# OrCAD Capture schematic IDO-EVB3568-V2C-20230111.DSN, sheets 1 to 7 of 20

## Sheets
1 P01. Revision History
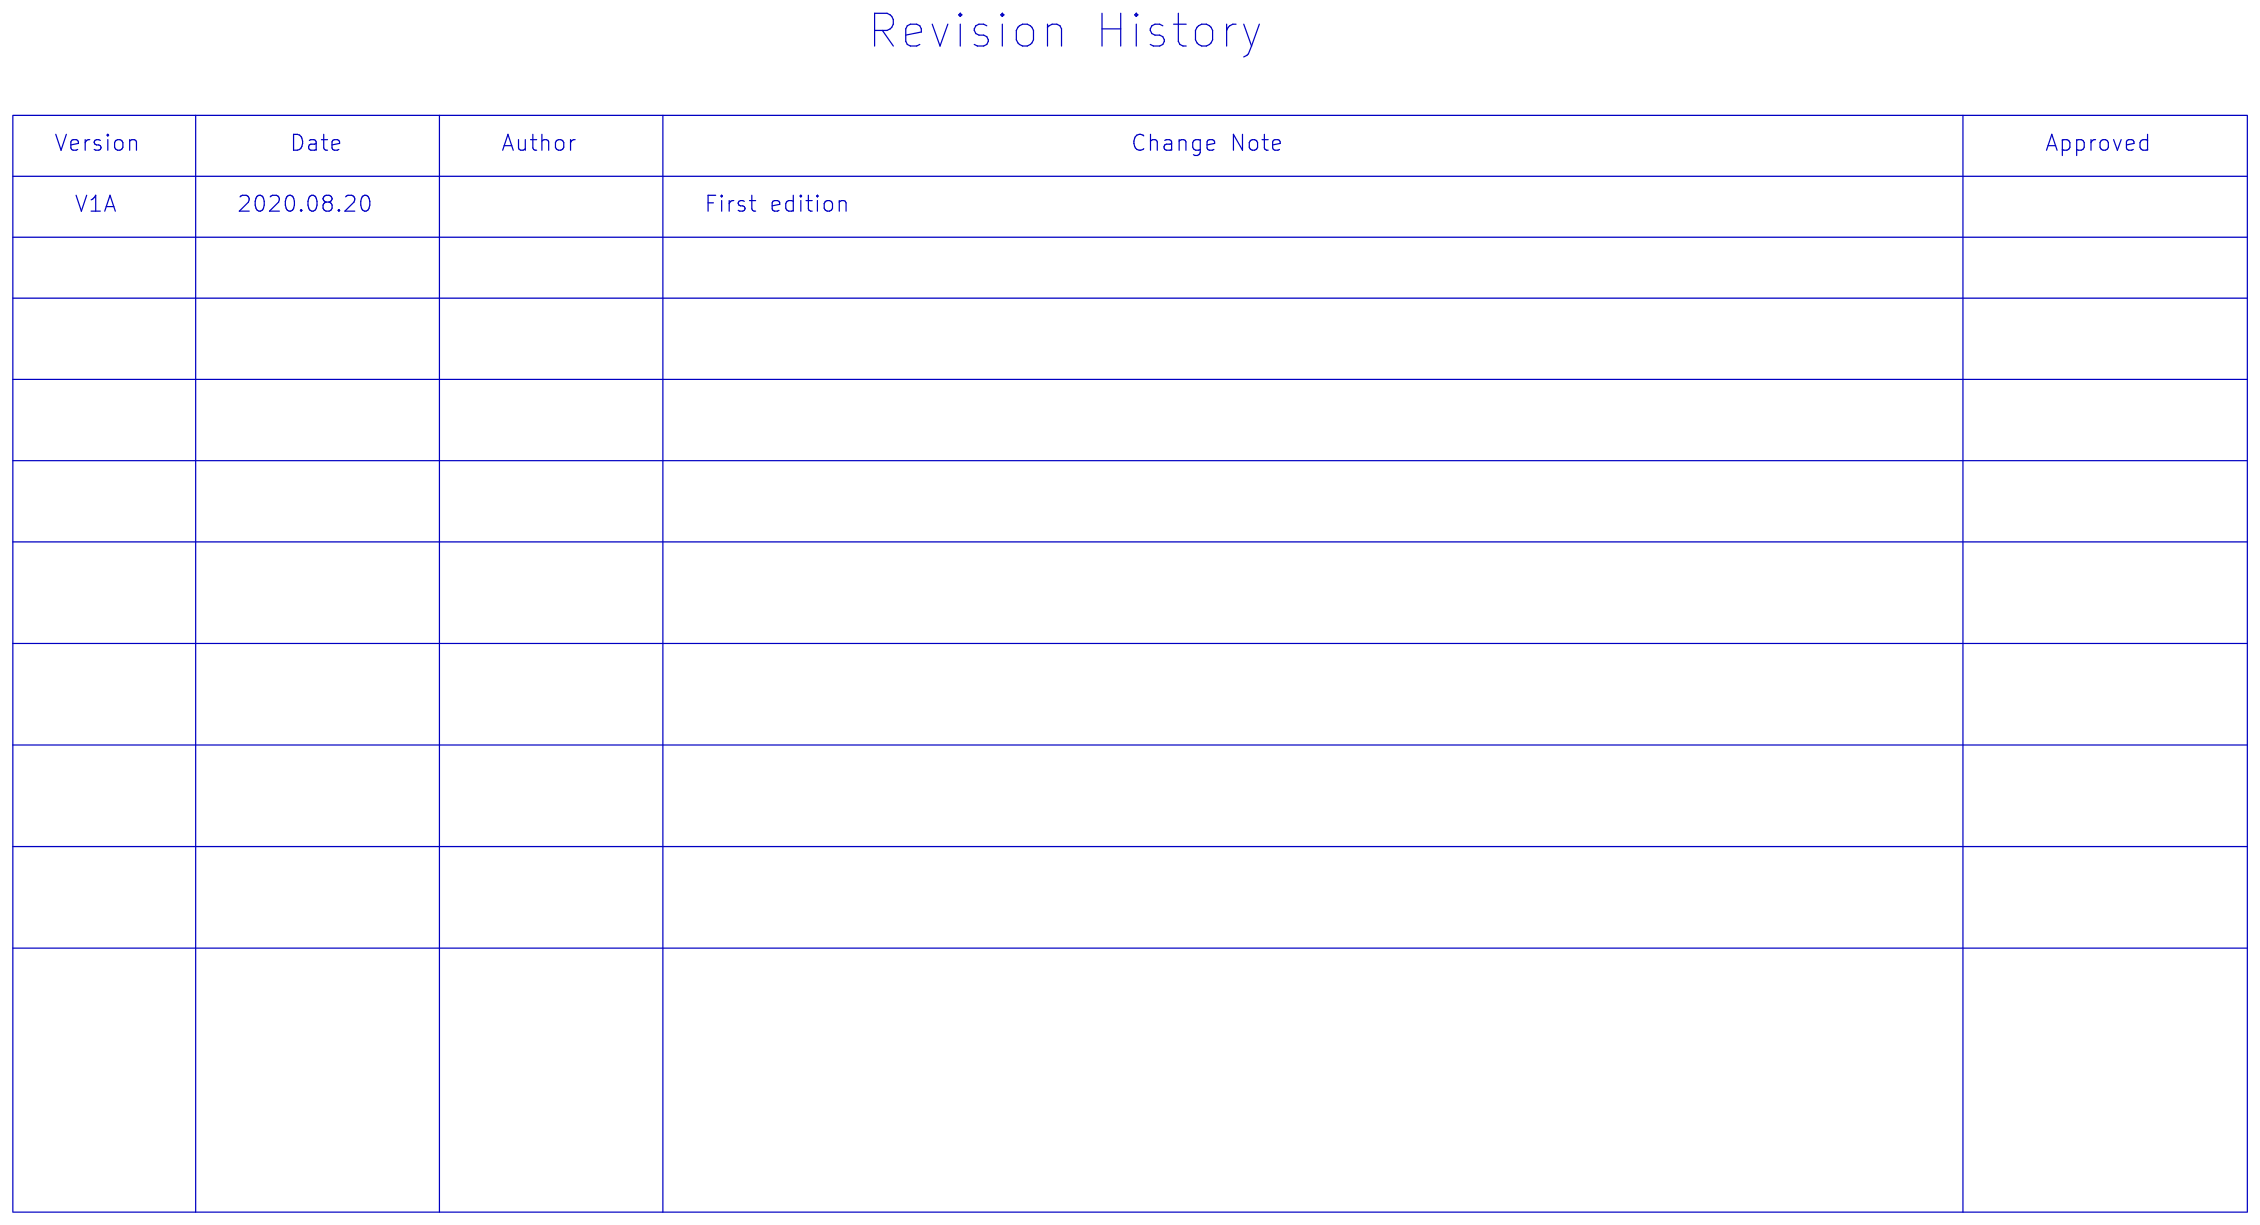
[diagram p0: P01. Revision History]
2 P02. Block Diagram: title: IDO-EVB3568-V1; note: Block Diagram
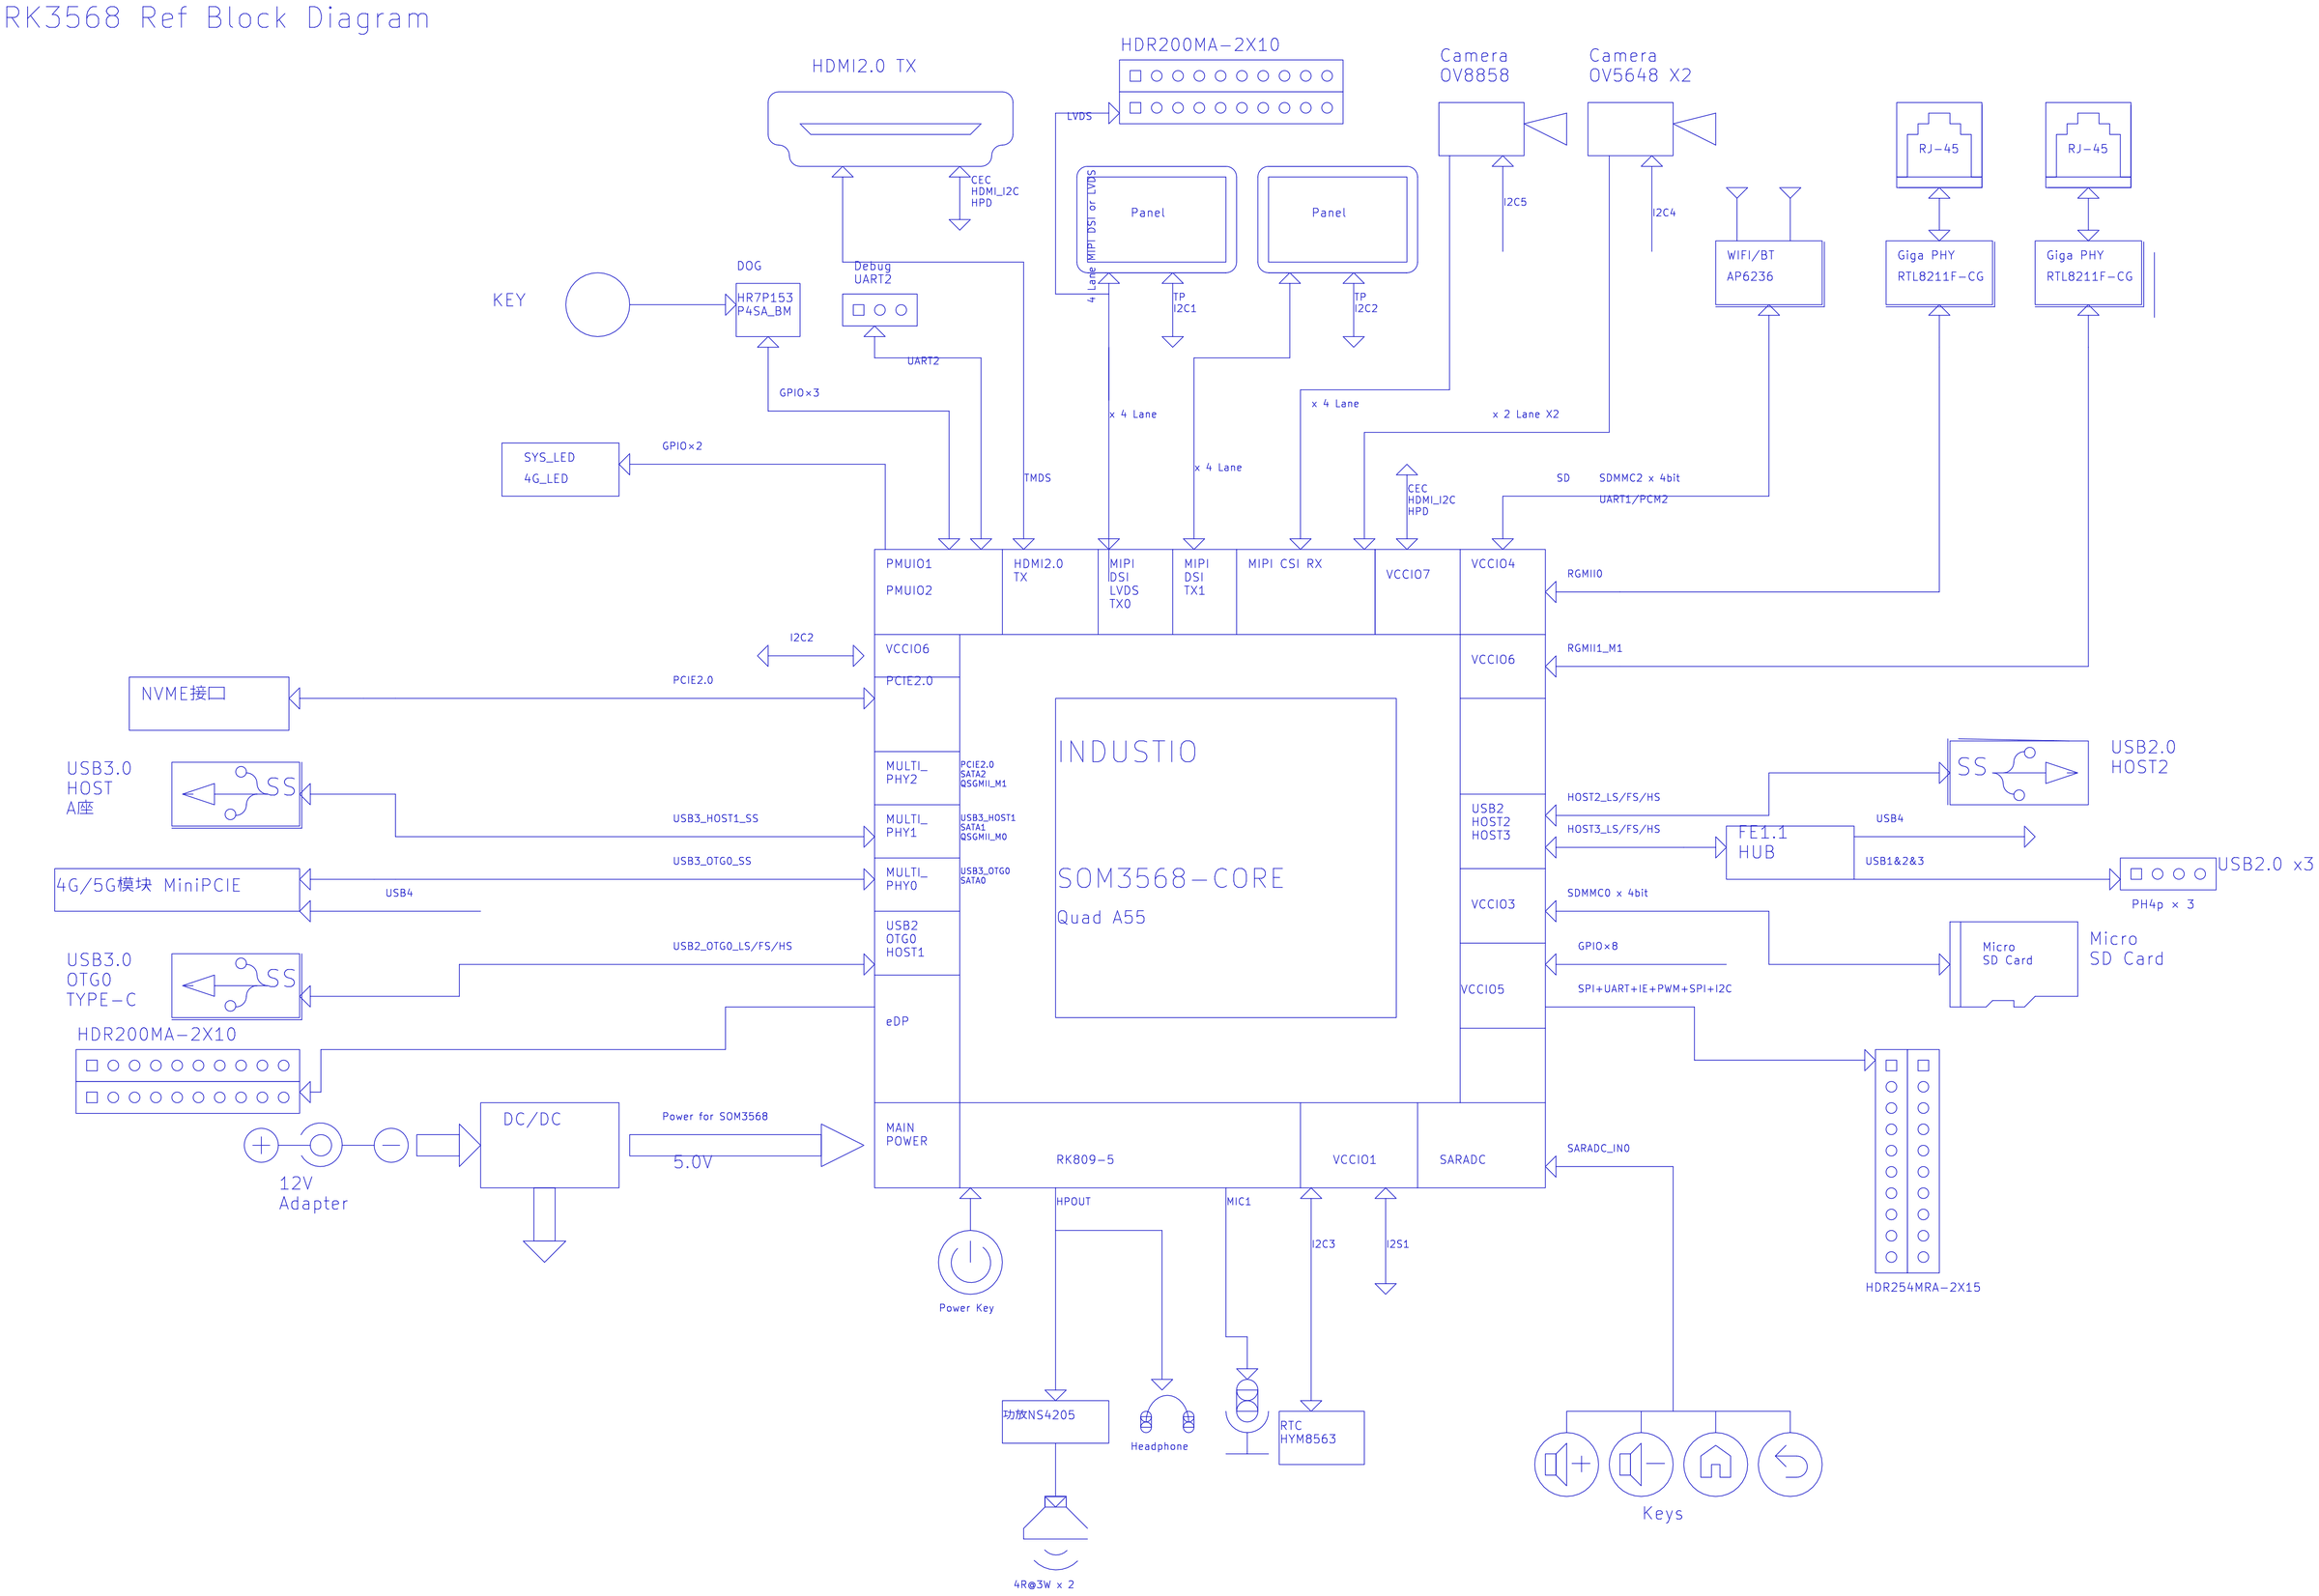
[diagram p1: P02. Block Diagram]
3 P03. Power Diagram: title: IDO-EVB3568-V2; note: Power Diagram
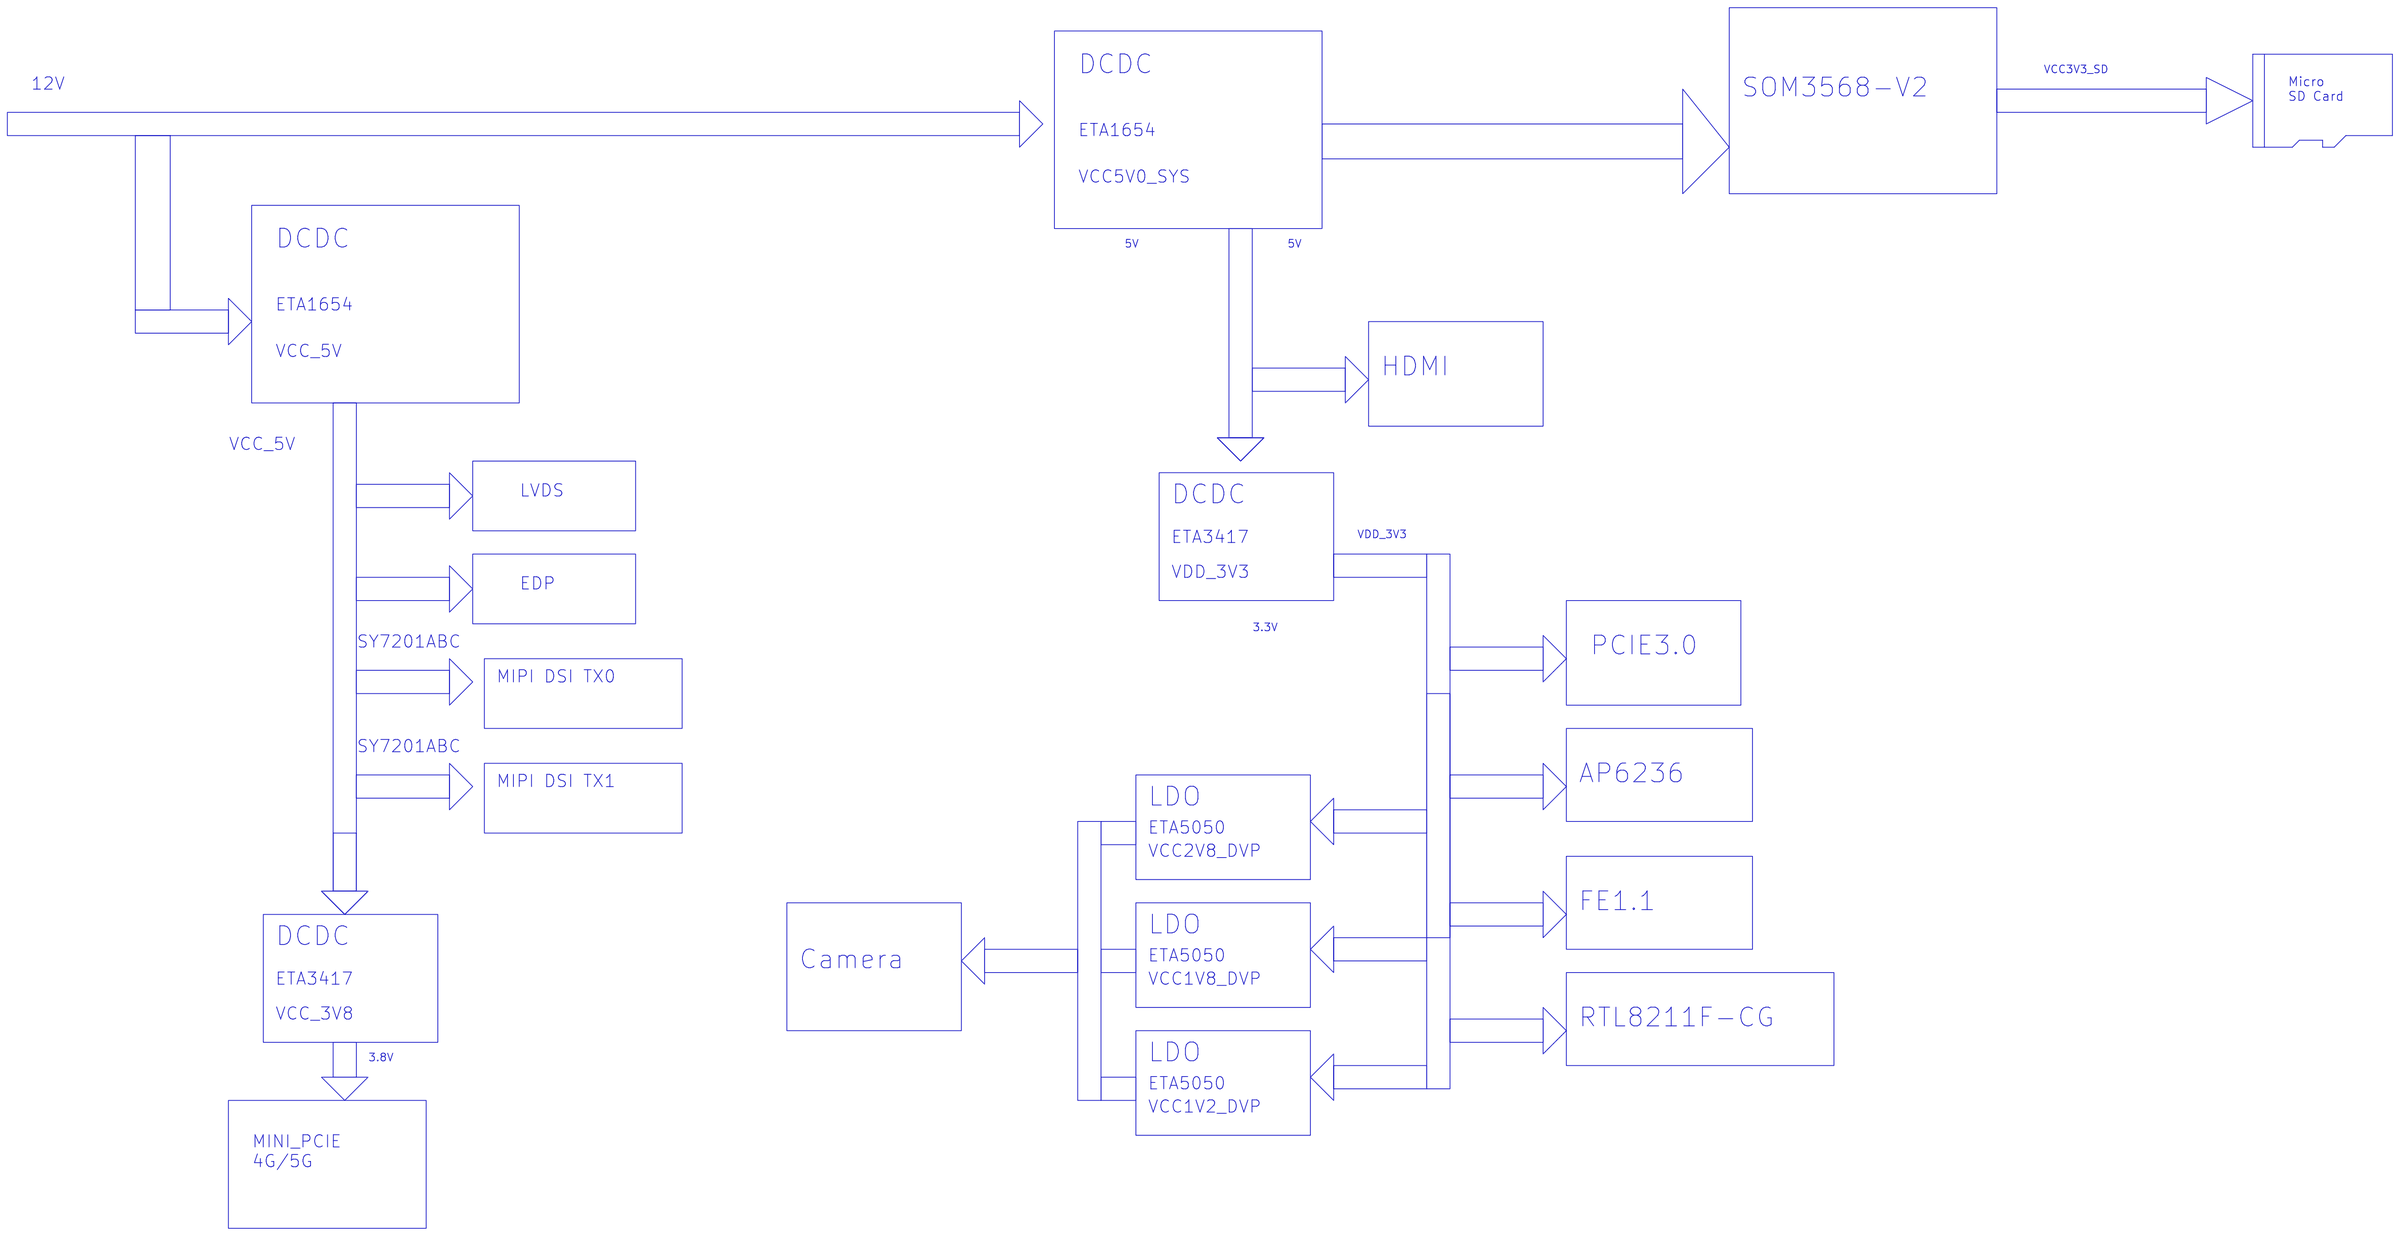
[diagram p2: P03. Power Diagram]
4 P04. Power_DC IN: size A3; title: IDO-EVB3568-V2; note: Power DC_IN
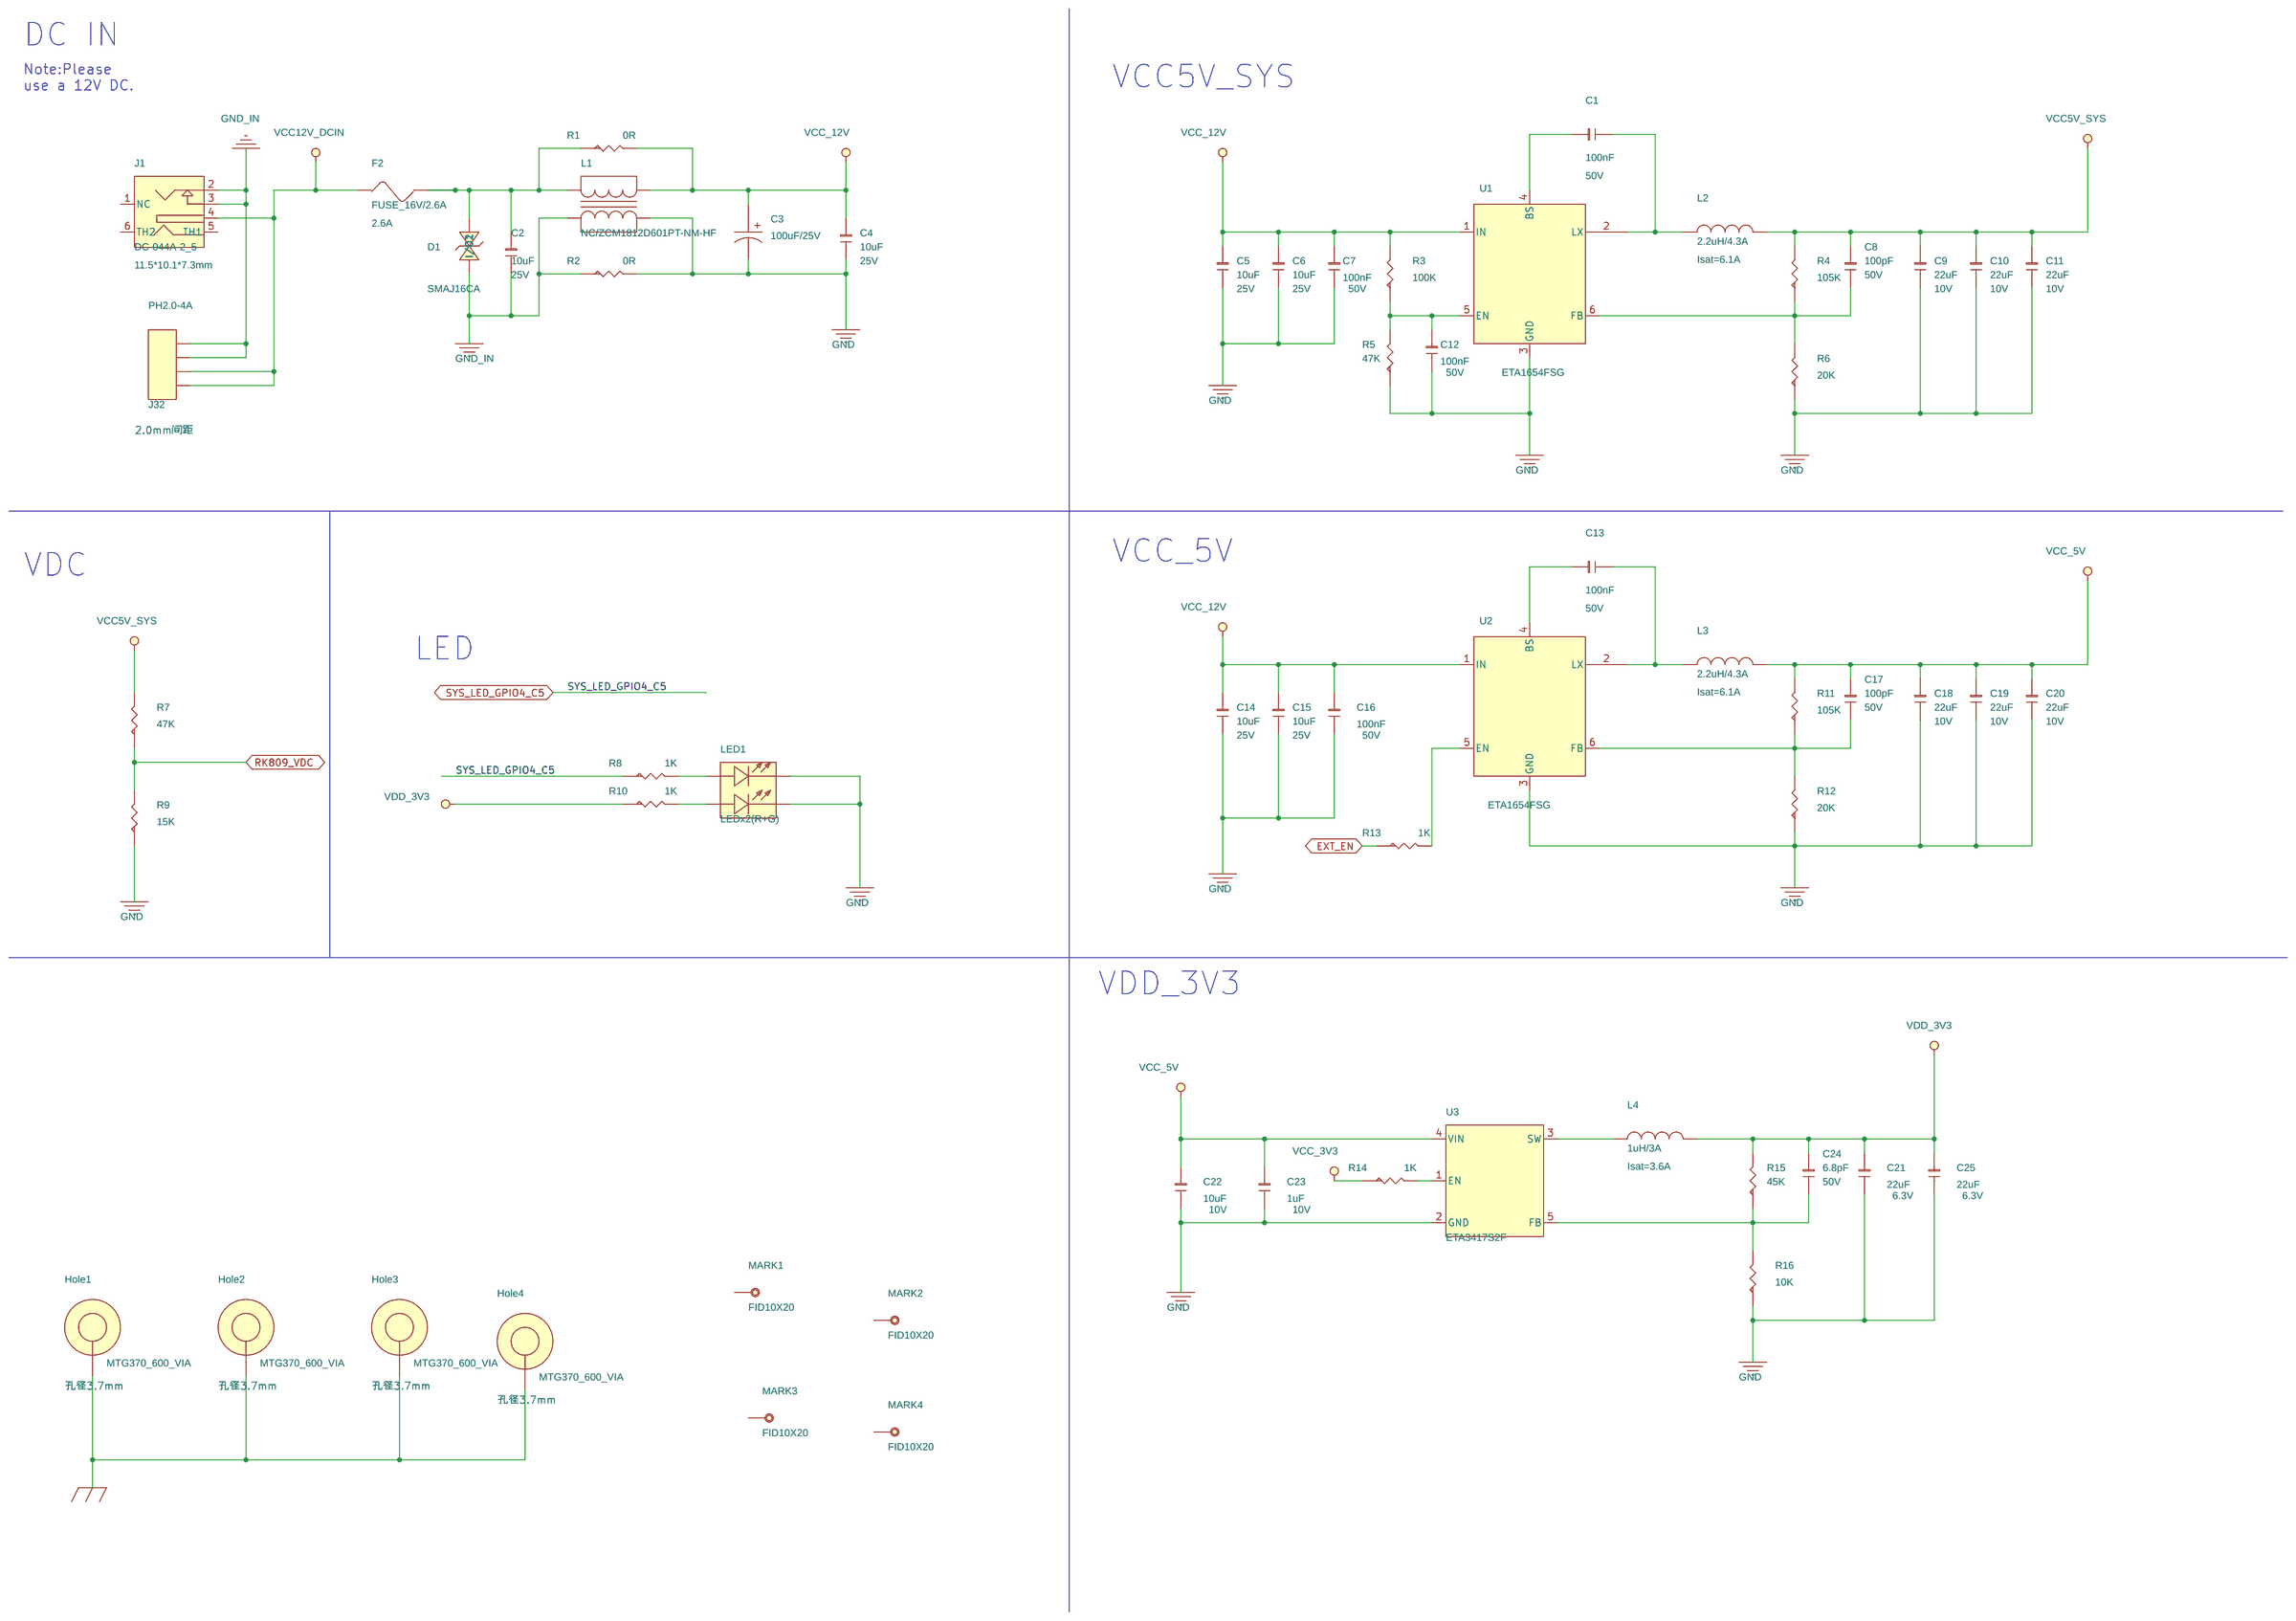
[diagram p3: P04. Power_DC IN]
5 P05. SOM3568-RK3568-Core: size A2; title: IDO-EVB3568-V2; note: SOM3568
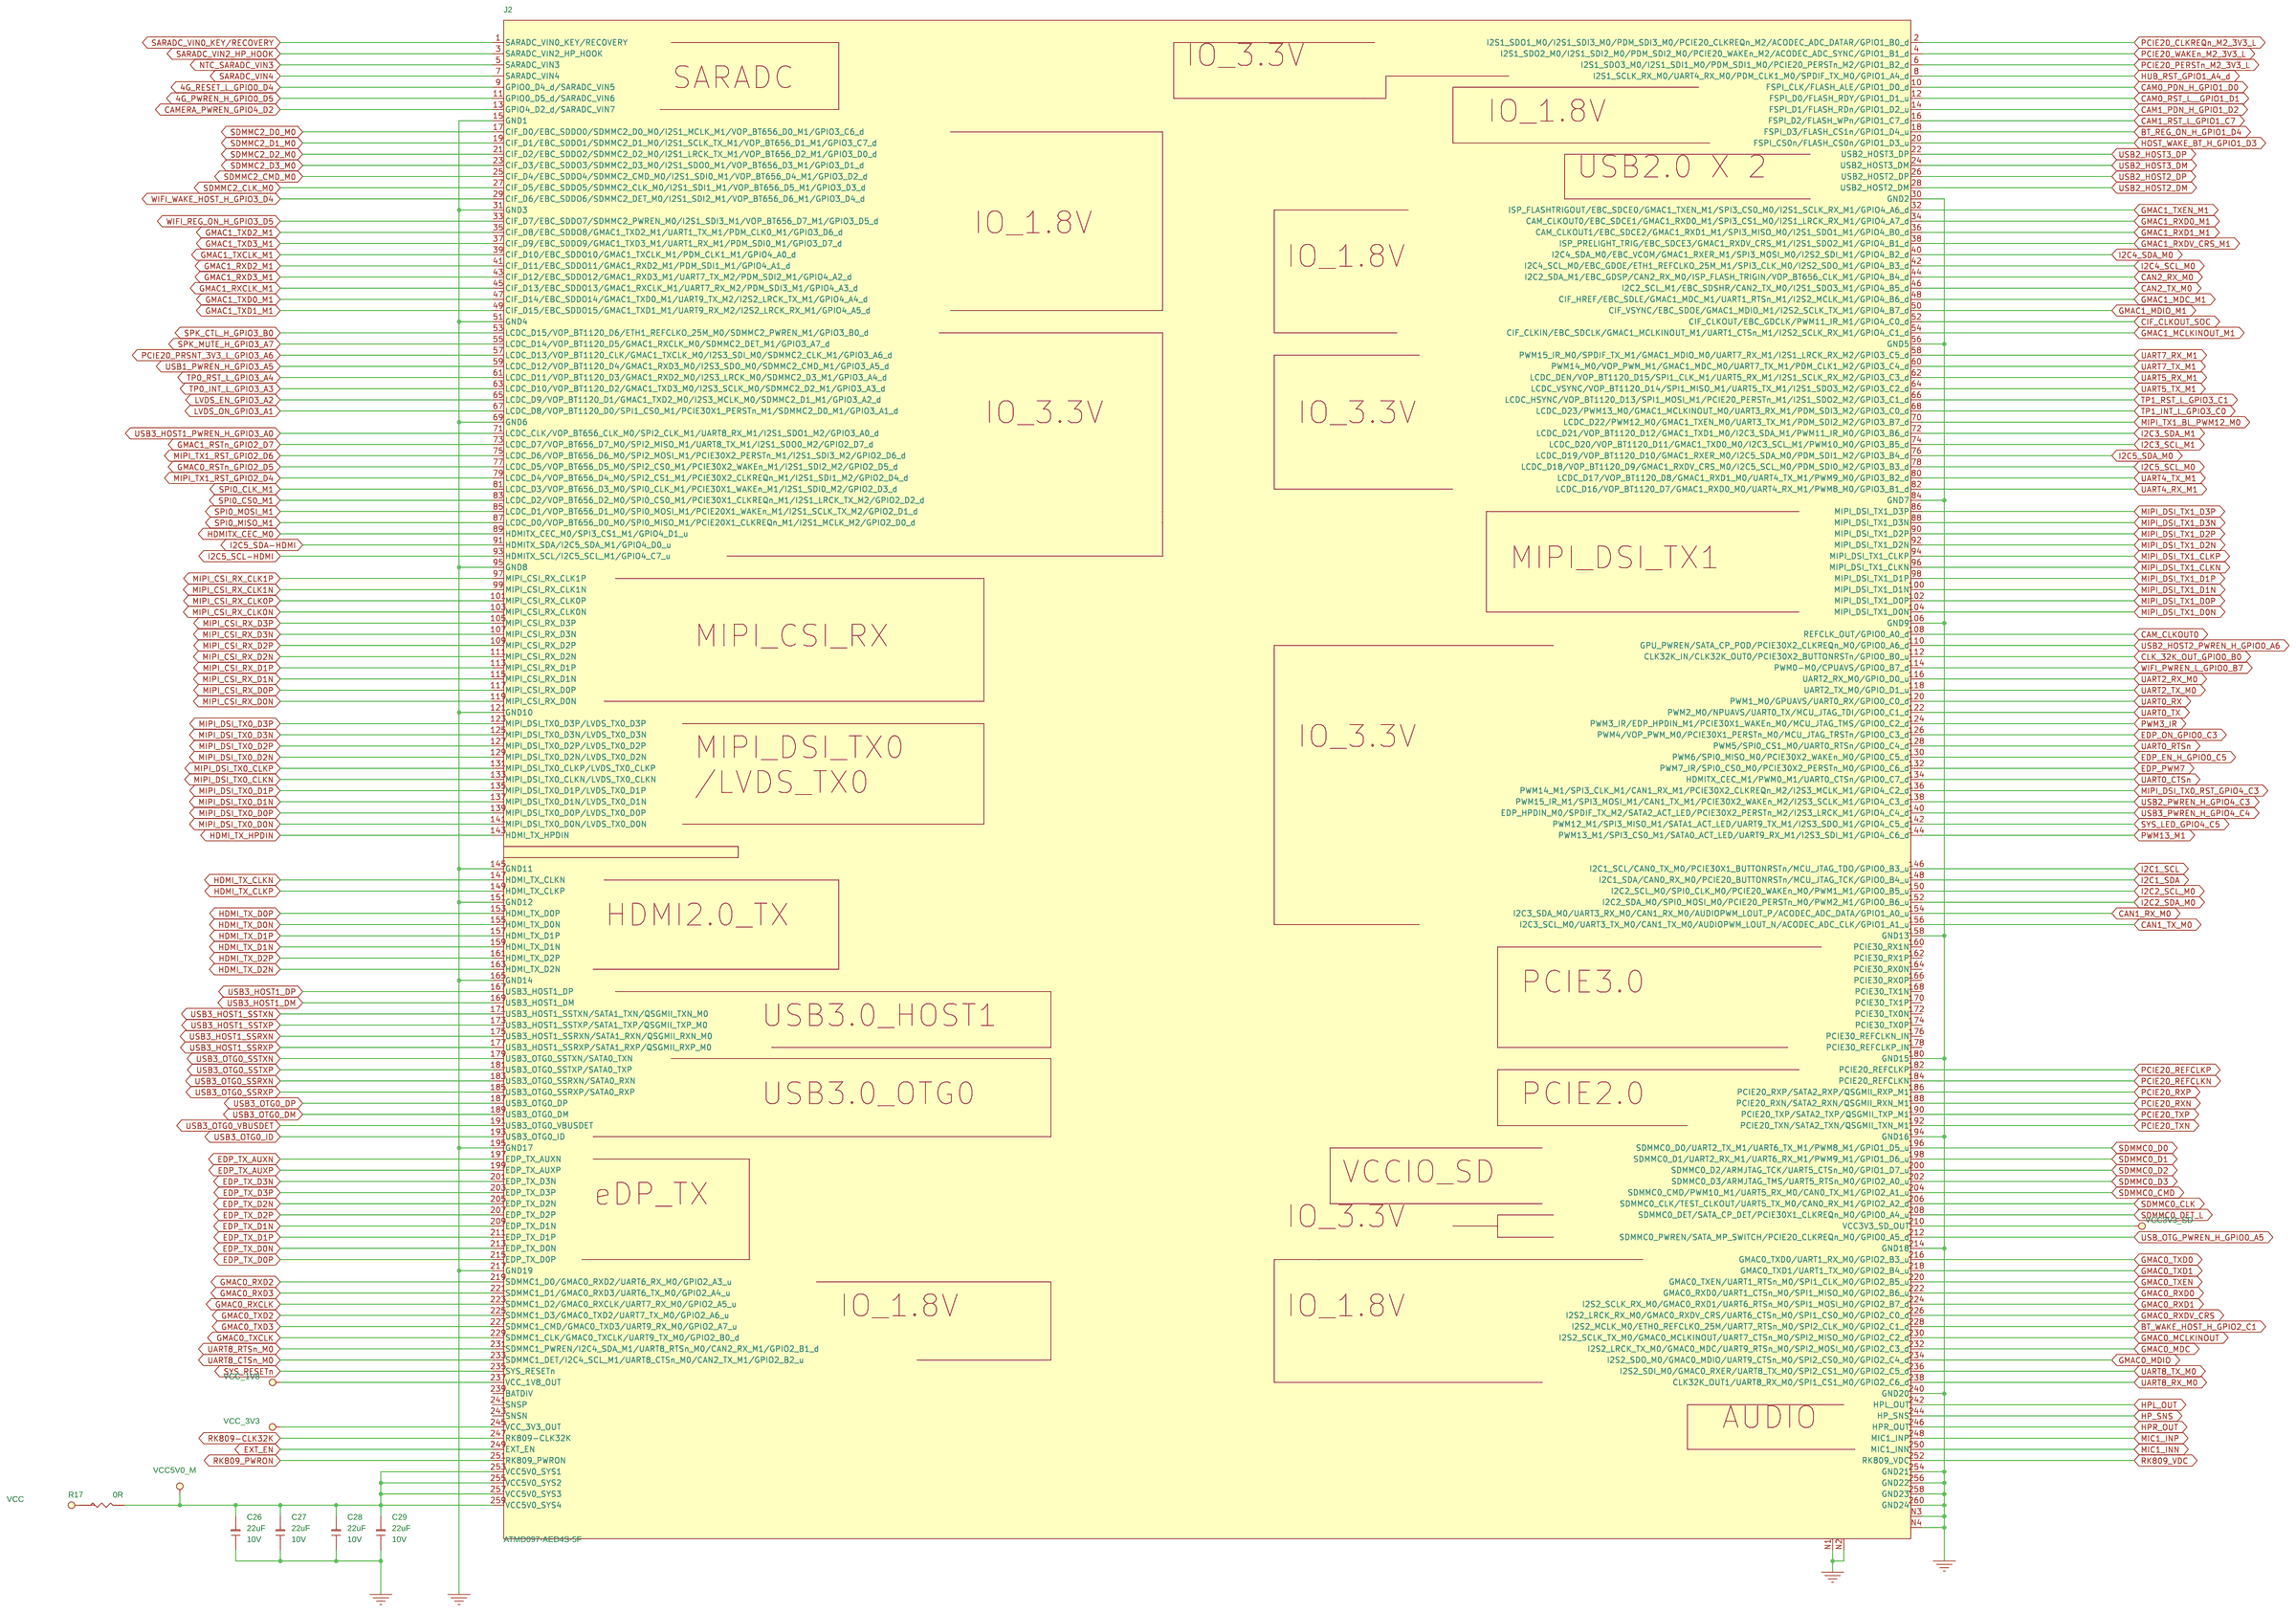
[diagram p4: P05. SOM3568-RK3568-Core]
6 P06. Flash-SD Card: size A4; title: IDO-EVB3568-V2; note: TF CARD & DEBUG
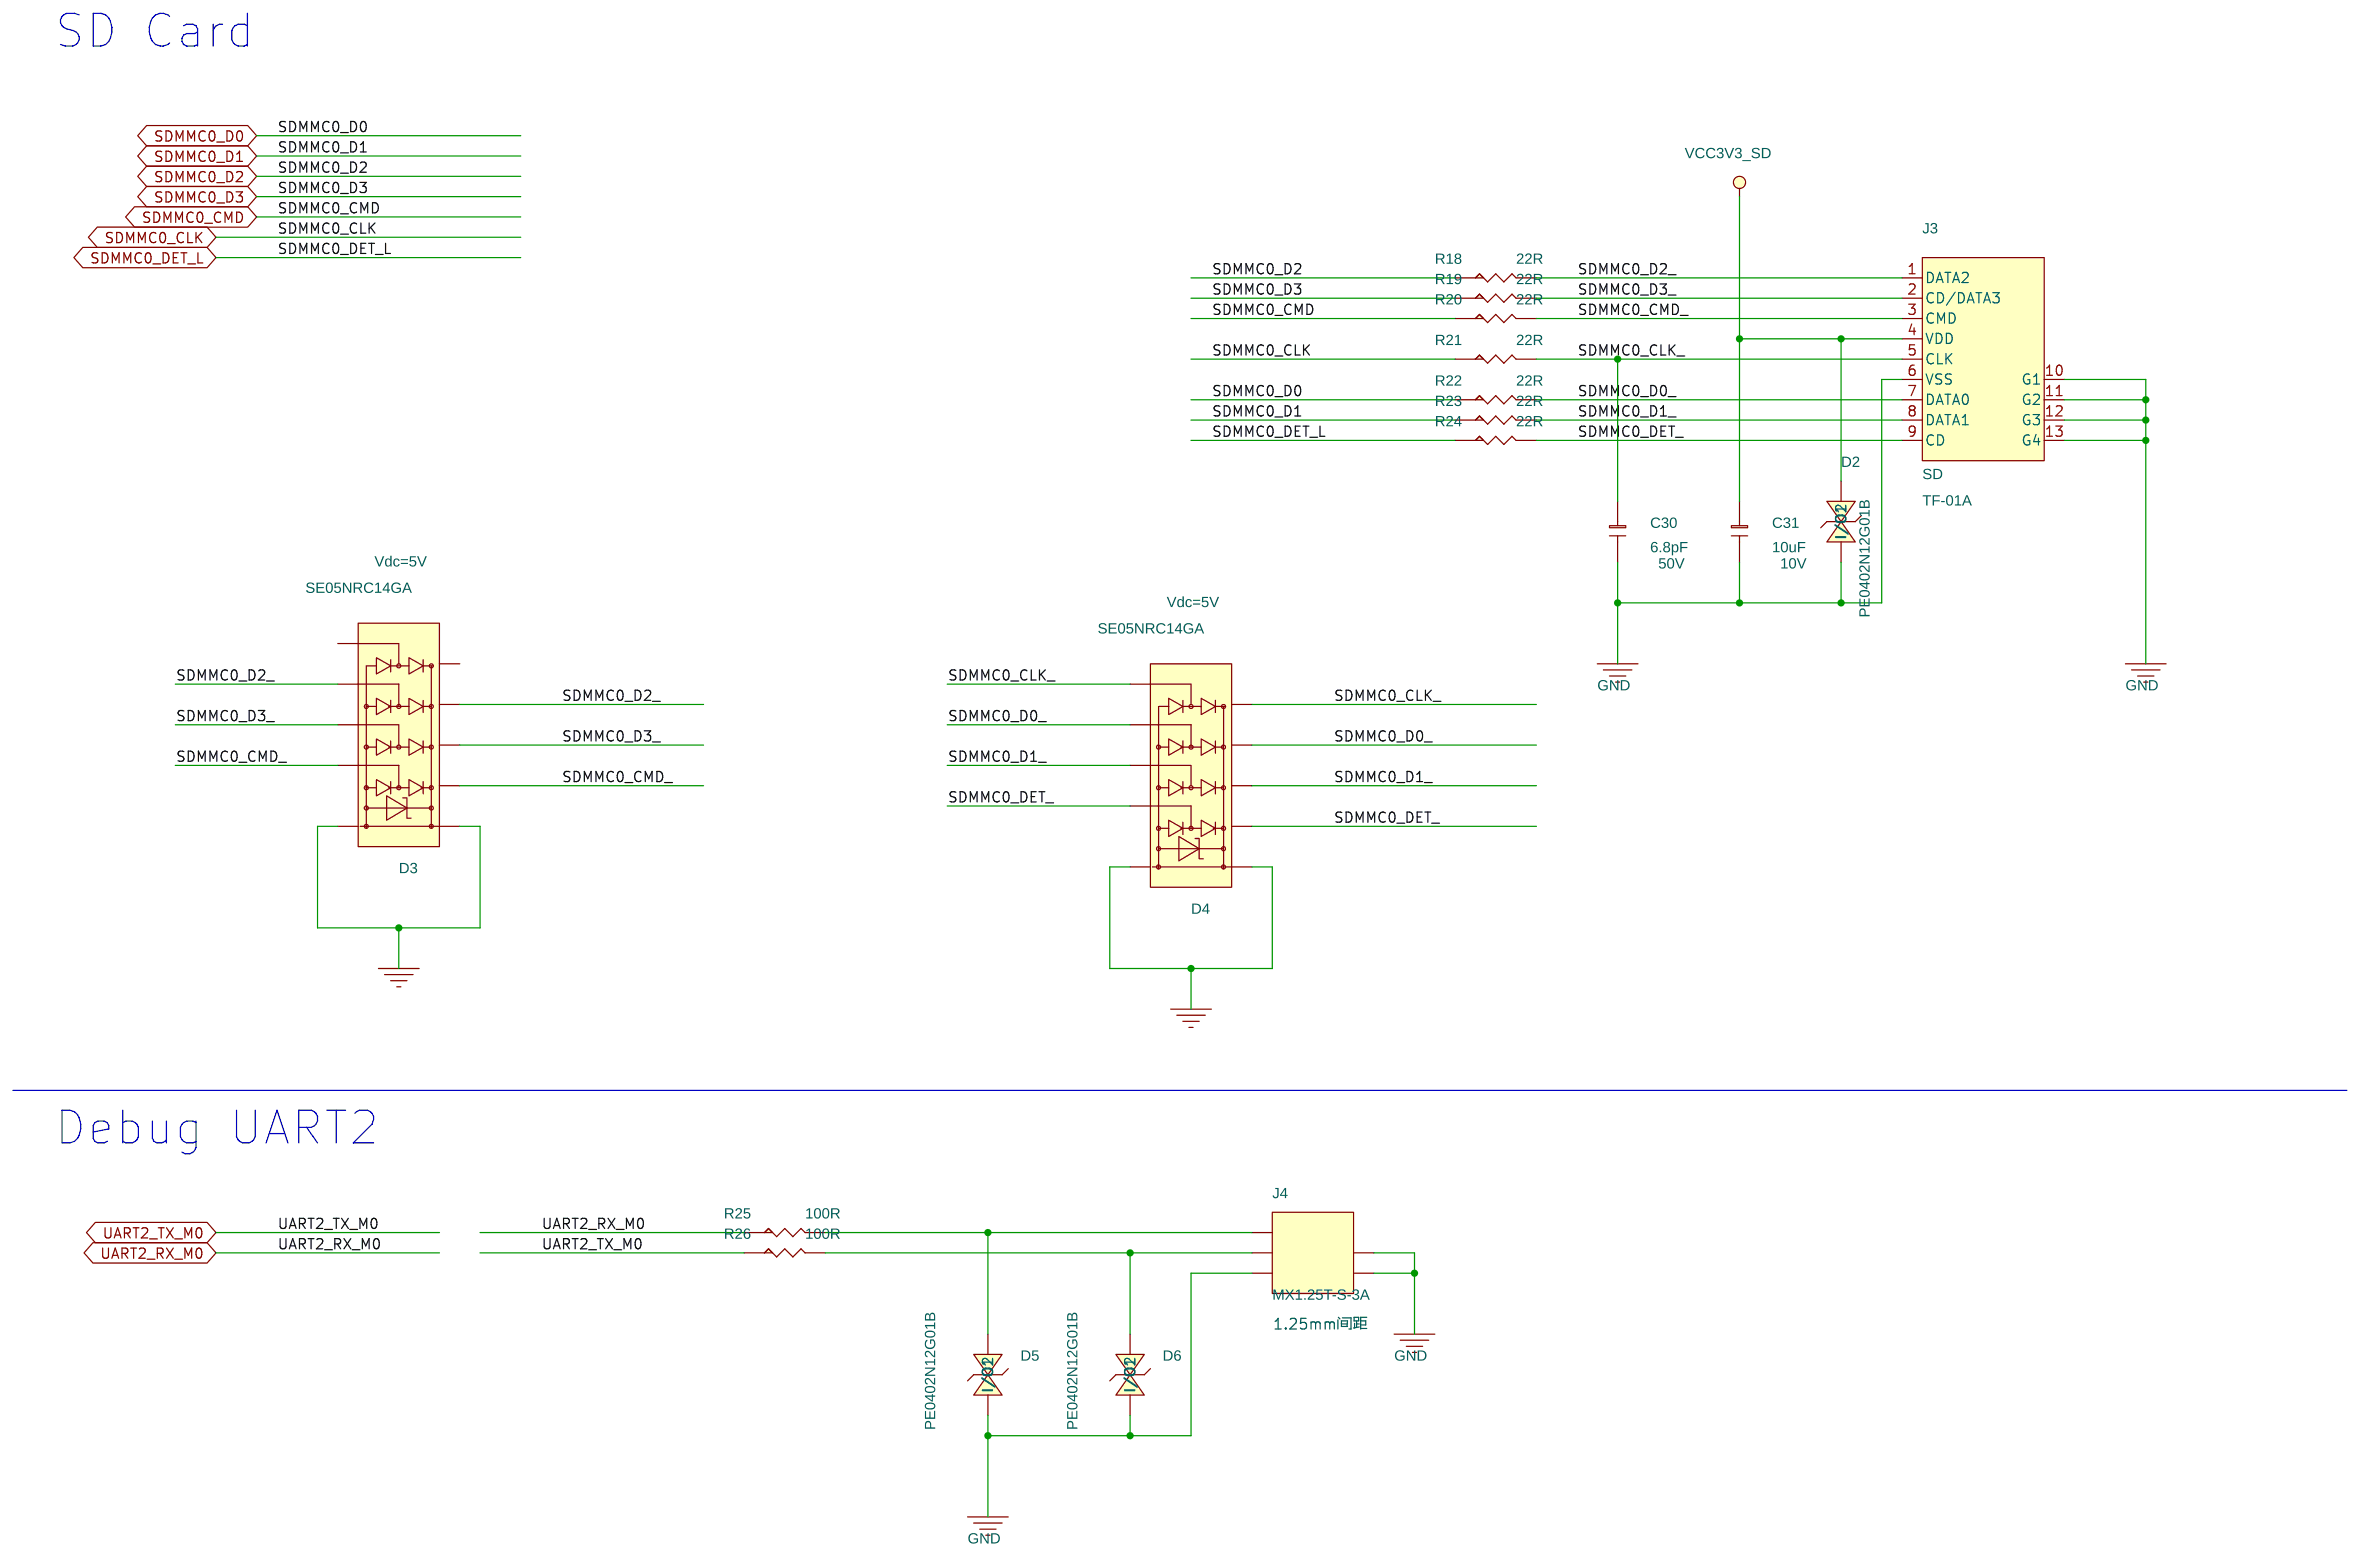
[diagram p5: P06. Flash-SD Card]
7 P07. USB Port: size A2; title: IDO-EVB3568-V2; note: USB PORT
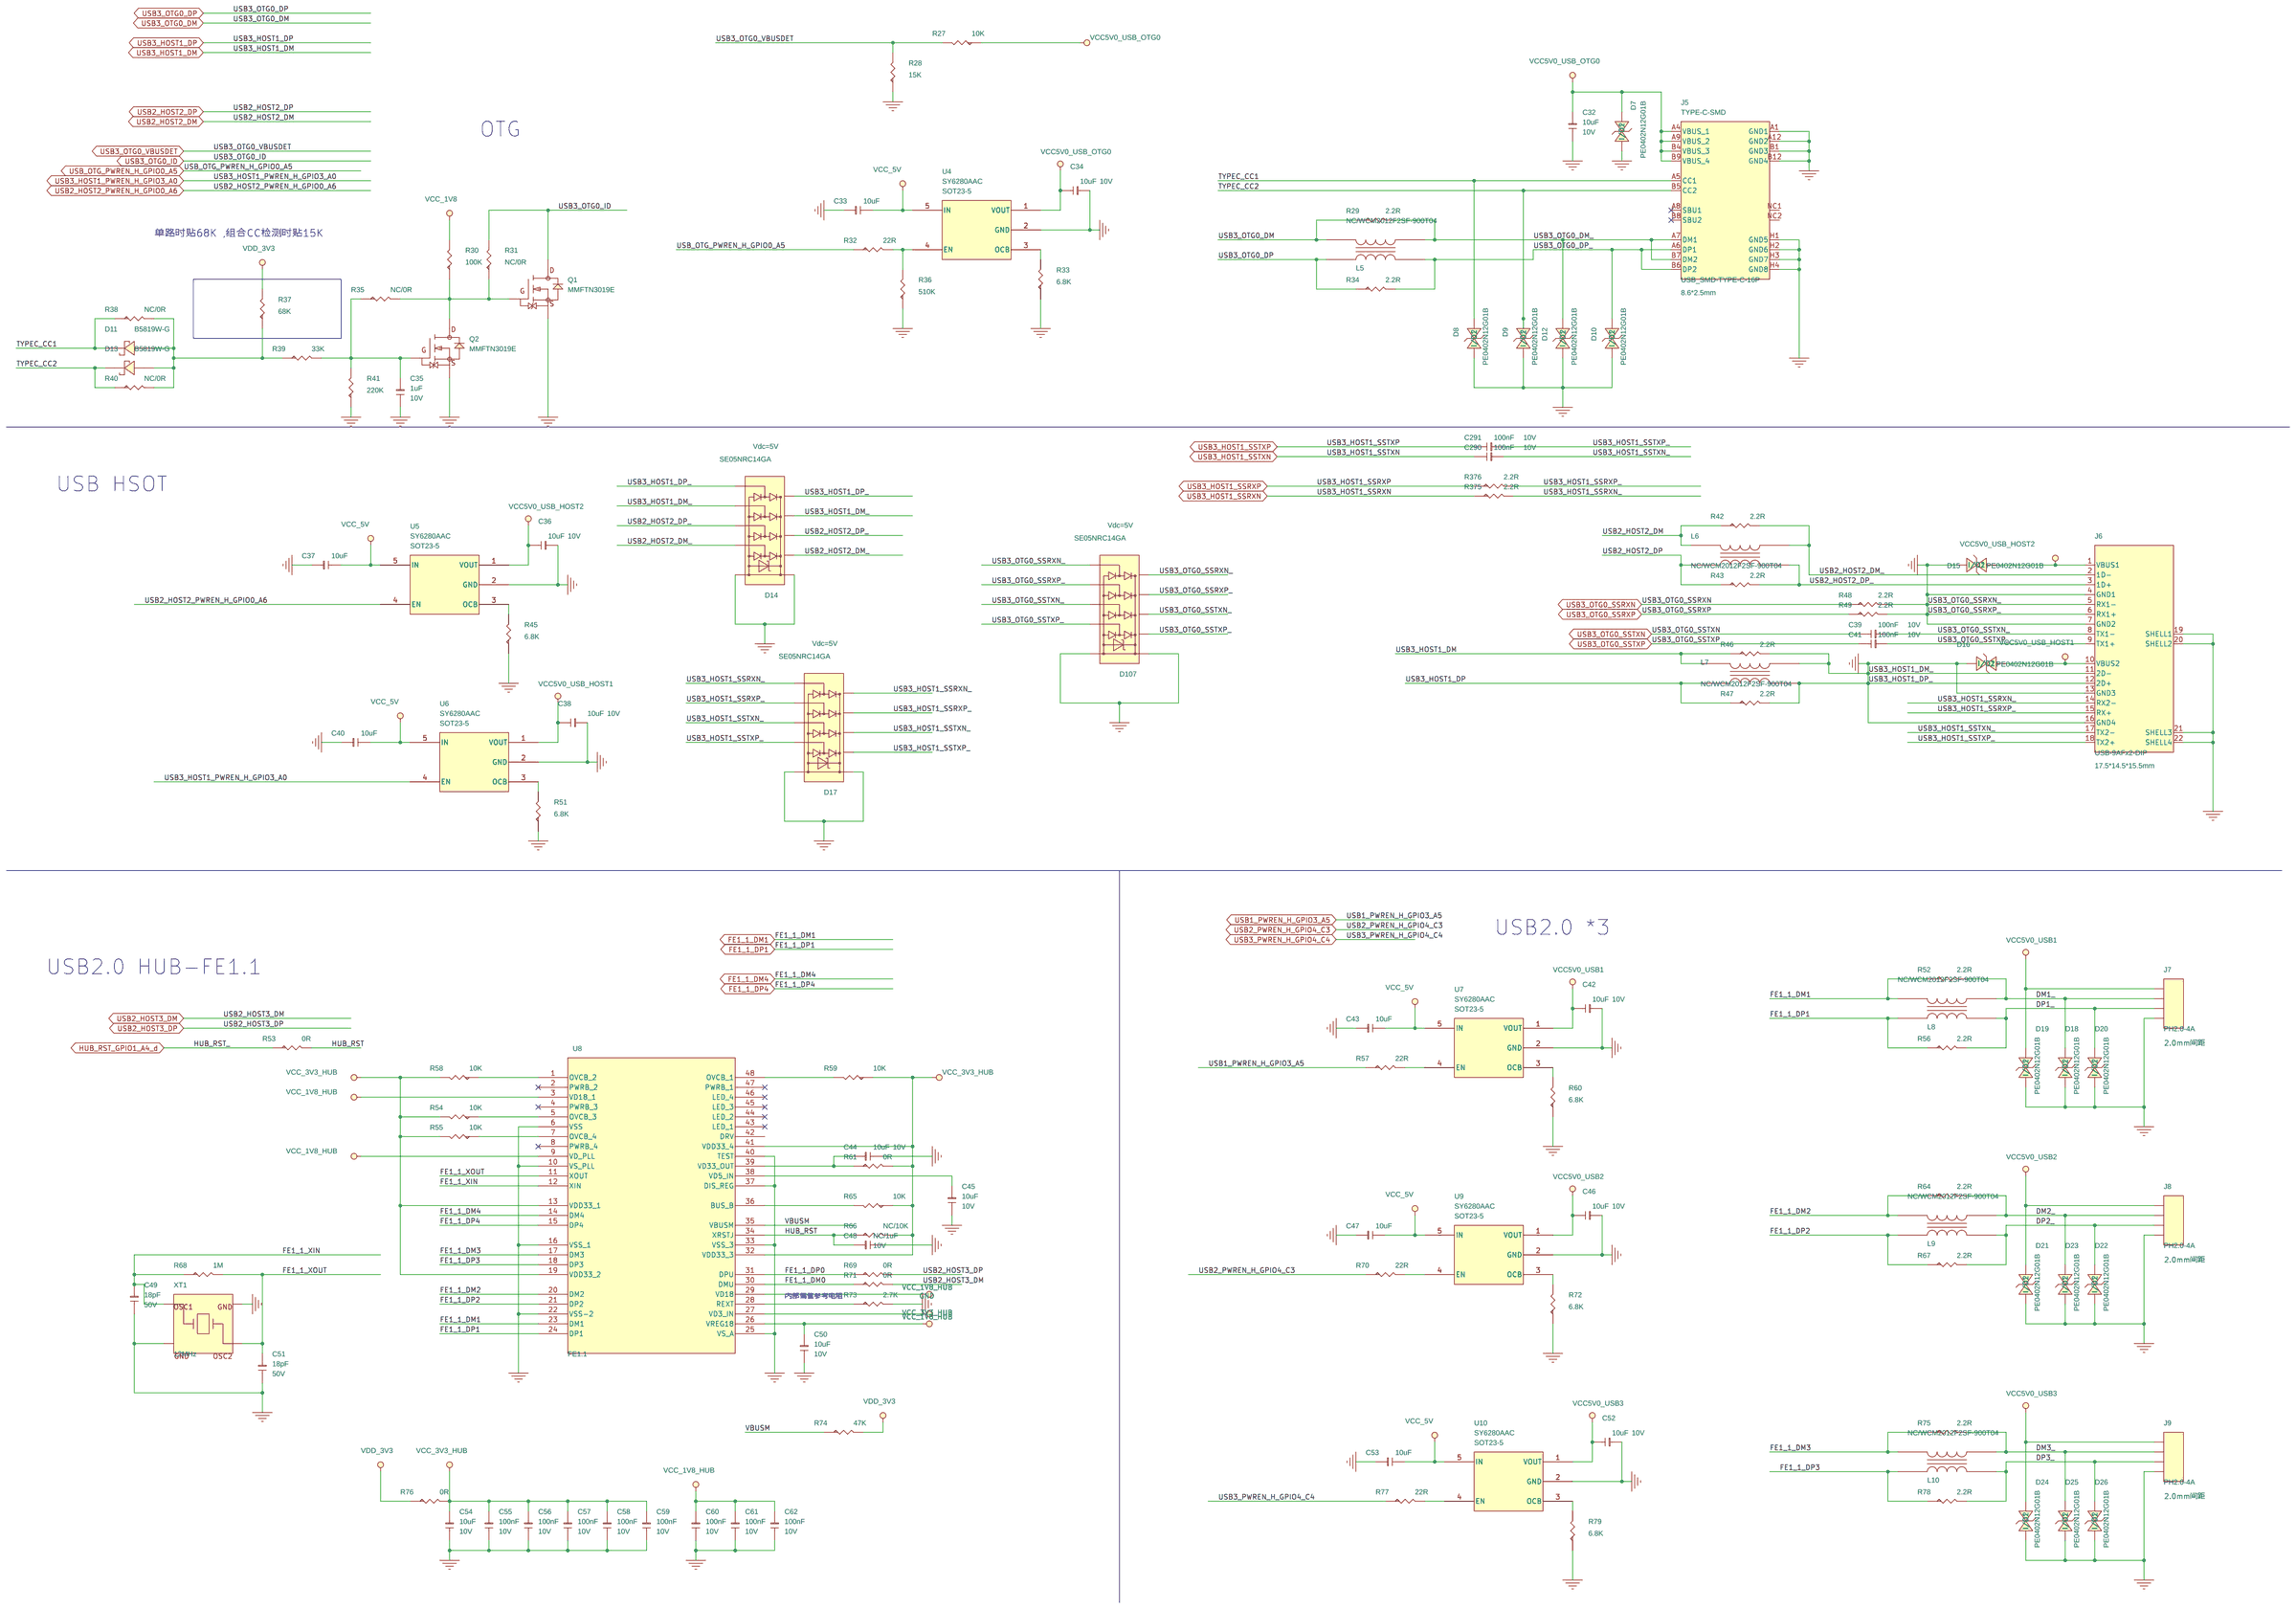
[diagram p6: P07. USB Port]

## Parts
sheet P04. Power_DC IN
C1  100nF  [C0402]
C2  10uF  [C0805]
C3  100uF/25V  [CAPAE660X770]
C4  10uF  [C0805]
C5  10uF  [C0805]
C6  10uF  [C0805]
C7  100nF  [C0402]
C8  100pF  [C0402]
C9  22uF  [C0603]
C10  22uF  [C0603]
C11  22uF  [C0603]
C12  100nF  [C0402]
C13  100nF  [C0402]
C14  10uF  [C0805]
C15  10uF  [C0805]
C16  100nF  [C0402]
C17  100pF  [C0402]
C18  22uF  [C0603]
C19  22uF  [C0603]
C20  22uF  [C0603]
C21  22uF  [C0603]
C22  10uF  [C0603]
C23  1uF  [C0402]
C24  6.8pF  [C0402]
C25  22uF  [C0603]
D1  SMAJ16CA  [SMA_DO-214AC]
F2  FUSE_16V/2.6A  [SMD1812]
Hole1  MTG370_600_VIA  [MTG370_600_VIA]
Hole2  MTG370_600_VIA  [MTG370_600_VIA]
Hole3  MTG370_600_VIA  [MTG370_600_VIA]
Hole4  MTG370_600_VIA  [MTG370_600_VIA]
J1  DC-044A-2_5  [DC-044A-2_0-DIP]
J32  PH2.0-4A  [PH200-4A]
L1  NC/ZCM1812D601PT-NM-HF  [CMLP-ACM4532]
L2  2.2uH/4.3A  [IND_404020]
L3  2.2uH/4.3A  [IND_404020]
L4  1uH/3A  [IND_252012]
LED1  LEDx2(R+G)  [LED_P254_2X2DIP]
MARK1  FID10X20  [FID1_0x2_3]
MARK2  FID10X20  [FID1_0x2_3]
MARK3  FID10X20  [FID1_0x2_3]
MARK4  FID10X20  [FID1_0x2_3]
R1  0R  [R0805]
R2  0R  [R0805]
R3  100K  [R0402]
R4  105K  [R0402]
R5  47K  [R0402]
R6  20K  [R0402]
R7  47K  [R0402]
R8  1K  [R0402]
R9  15K  [R0402]
R10  1K  [R0402]
R11  105K  [R0402]
R12  20K  [R0402]
R13  1K  [R0402]
R14  1K  [R0402]
R15  45K  [R0402]
R16  10K  [R0402]
U1  ETA1654FSG  [SOT563]
U2  ETA1654FSG  [SOT563]
U3  ETA3417S2F  [SOT23-5]
sheet P05. SOM3568-RK3568-Core
C26  22uF  [C0603]
C27  22uF  [C0603]
C28  22uF  [C0603]
C29  22uF  [C0603]
J2  ATMD097-AED4S-5F  [DDR4-SODIMM-260P-STD]
R17  0R  [R0805]
sheet P06. Flash-SD Card
C30  6.8pF  [C0402]
C31  10uF  [C0603]
D2  PE0402N12G01B  [V0402]
D3  SE05NRC14GA  [DFN2510-10L]
D4  SE05NRC14GA  [DFN2510-10L]
D5  PE0402N12G01B  [V0402]
D6  PE0402N12G01B  [V0402]
J3  SD  [TF-01A]
J4  MX1.25T-S-3A  [MX125T-S-3A]
R18  22R  [R0402]
R19  22R  [R0402]
R20  22R  [R0402]
R21  22R  [R0402]
R22  22R  [R0402]
R23  22R  [R0402]
R24  22R  [R0402]
R25  100R  [R0402]
R26  100R  [R0402]
sheet P07. USB Port
C32  10uF  [C0603]
C33  10uF  [C0603]
C34  10uF  [C0603]
C35  1uF  [C0402]
C36  10uF  [C0603]
C37  10uF  [C0603]
C38  10uF  [C0603]
C39  100nF  [C0402]
C40  10uF  [C0603]
C41  100nF  [C0402]
C42  10uF  [C0603]
C43  10uF  [C0603]
C44  10uF  [C0603]
C45  10uF  [C0603]
C46  10uF  [C0603]
C47  10uF  [C0603]
C48  NC/1uF  [C0402]
C49  18pF  [C0402]
C50  10uF  [C0603]
C51  18pF  [C0402]
C52  10uF  [C0603]
C53  10uF  [C0603]
C54  10uF  [C0603]
C55  100nF  [C0402]
C56  100nF  [C0402]
C57  100nF  [C0402]
C58  100nF  [C0402]
C59  100nF  [C0402]
C60  100nF  [C0402]
C61  100nF  [C0402]
C62  100nF  [C0402]
C290  100nF  [C0402]
C291  100nF  [C0402]
D7  PE0402N12G01B  [V0402]
D8  PE0402N12G01B  [V0402]
D9  PE0402N12G01B  [V0402]
D10  PE0402N12G01B  [V0402]
D11  B5819W-G  [SOD123]
D12  PE0402N12G01B  [V0402]
D13  B5819W-G  [SOD123]
D14  SE05NRC14GA  [DFN2510-10L]
D15  PE0402N12G01B  [V0402]
D16  PE0402N12G01B  [V0402]
D17  SE05NRC14GA  [DFN2510-10L]
D18  PE0402N12G01B  [V0402]
D19  PE0402N12G01B  [V0402]
D20  PE0402N12G01B  [V0402]
D21  PE0402N12G01B  [V0402]
D22  PE0402N12G01B  [V0402]
D23  PE0402N12G01B  [V0402]
D24  PE0402N12G01B  [V0402]
D25  PE0402N12G01B  [V0402]
D26  PE0402N12G01B  [V0402]
D107  SE05NRC14GA  [DFN2510-10L]
J5  TYPE-C-SMD  [USB_SMD-TYPE-C-16P]
J6  USB-9AFx2-DIP  [USB-9AF-DIP_2x]
J7  PH2.0-4A  [PH200-4A]
J8  PH2.0-4A  [PH200-4A]
J9  PH2.0-4A  [PH200-4A]
L5  NC/WCM2012F2SF-900T04  [CMLS-ACM2012]
L6  NC/WCM2012F2SF-900T04  [CMLS-ACM2012]
L7  NC/WCM2012F2SF-900T04  [CMLS-ACM2012]
L8  NC/WCM2012F2SF-900T04  [CMLS-ACM2012]
L9  NC/WCM2012F2SF-900T04  [CMLS-ACM2012]
L10  NC/WCM2012F2SF-900T04  [CMLS-ACM2012]
Q1  MMFTN3019E  [SOT523]
Q2  MMFTN3019E  [SOT523]
R27  10K  [R0402]
R28  15K  [R0402]
R29  2.2R  [R0402]
R30  100K  [R0402]
R31  NC/0R  [R0402]
R32  22R  [R0402]
R33  6.8K  [R0402]
R34  2.2R  [R0402]
R35  NC/0R  [R0402]
R36  510K  [R0402]
R37  68K  [R0402]
R38  NC/0R  [R0402]
R39  33K  [R0402]
R40  NC/0R  [R0402]
R41  220K  [R0402]
R42  2.2R  [R0402]
R43  2.2R  [R0402]
R45  6.8K  [R0402]
R46  2.2R  [R0402]
R47  2.2R  [R0402]
R48  2.2R  [R0402]
R49  2.2R  [R0402]
R51  6.8K  [R0402]
R52  2.2R  [R0402]
R53  0R  [R0402]
R54  10K  [R0402]
R55  10K  [R0402]
R56  2.2R  [R0402]
R57  22R  [R0402]
R58  10K  [R0402]
R59  10K  [R0402]
R60  6.8K  [R0402]
R61  0R  [R0402]
R64  2.2R  [R0402]
R65  10K  [R0402]
R66  NC/10K  [R0402]
R67  2.2R  [R0402]
R68  1M  [R0402]
R69  0R  [R0402]
R70  22R  [R0402]
R71  0R  [R0402]
R72  6.8K  [R0402]
R73  2.7K  [R0402]
R74  47K  [R0402]
R75  2.2R  [R0402]
R76  0R  [R0402]
R77  22R  [R0402]
R78  2.2R  [R0402]
R79  6.8K  [R0402]
R375  2.2R  [R0402]
R376  2.2R  [R0402]
U4  SY6280AAC  [SOT23-5]
U5  SY6280AAC  [SOT23-5]
U6  SY6280AAC  [SOT23-5]
U7  SY6280AAC  [SOT23-5]
U8  FE1.1  [LQFP-48_7x7x05P]
U9  SY6280AAC  [SOT23-5]
U10  SY6280AAC  [SOT23-5]
XT1  12MHz  [xtal_32x25_4p]

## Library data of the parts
C1 C7 C12 C13 C16 = C-0402: DSC1: ±10%; DSC2: 50V; DSC3: X7R; ERP Number: 1010200128; ID: 61; Manufacture: 三星|国巨|村田; Part Name: 贴片电容; Part Number: C020102120061; Price: 0.05
C2 C4-C6 C14 C15 = C-0805: DSC1: ±10%; DSC2: 25V; DSC3: X5R; ERP Number: 1010200144; ID: 74; Manufacture: 三星|国巨|村田; Part Name: 贴片电容; Part Number: C020102120074; Price: 0.09
C3 = C-AL-SMD: DSC1: ±20%; DSC2: 25V; DSC3: 低阻抗; DSC4: 2000H; DSC5: -55~105 ℃; DSC6: SMD,6.3x7.7mm; DSC7: LZ1E101M-CRE77(ST); ERP Number: 1010200266; ID: 6; Manufacture: 先科|立隆|三莹; Part Name: 贴片铝电容; Part Number: C020302140006; Price: 0.20
C8 C17 = C-0402: DSC1: ±5%; DSC2: 50V; DSC3: C0G; ERP Number: 1010200152; ID: 40; Manufacture: 三星|国巨|村田; Part Name: 贴片电容; Part Number: C020102120040; Price: 0.01
C9-C11 C18-C20 C26-C29 = C-0805: DSC1: ±20%; DSC2: 10V; DSC3: X5R; ID: 75; Manufacture: 三星|国巨|村田; Part Name: 贴片电容; Part Number: C020102120075; Price: 0.11
C21 C25 = C-0603: DSC1: ±20%; DSC2: 6.3V; DSC3: X5R; ERP Number: 1010200133; ID: 72; Manufacture: 三星|国巨|村田; Part Name: 贴片电容; Part Number: C020102120072; Price: 0.06
C22 C31-C34 C36-C38 C40 C42-C47 C50 C52-C54 = C-0603: DSC1: ±20%; DSC2: 10V; DSC3: X5R; ERP Number: 1010200076; ID: 71; Manufacture: 三星|国巨|村田; Part Name: 贴片电容; Part Number: C020102120071; Price: 0.05
C23 C35 C48 = C-0402: DSC1: ±10%; DSC2: 10V; DSC3: X5R; ERP Number: 1010200054; ID: 64; Manufacture: 三星|国巨|村田; Part Name: 贴片电容; Part Number: C020102120064; Price: 0.02
C24 C30 = C-0402: DSC1: ±0.25PF; DSC2: 50V; DSC3: C0G; ERP Number: 1010200056; ID: 18; Manufacture: 三星|国巨|村田; Part Name: 贴片电容; Part Number: C020102120018; Price: 0.01
D1 = DI-TVS-D: DSC1: 双向; DSC2: Vrwm=16V; DSC3: VBR=17.8V; DSC4: Vc=26V; DSC5: Ipp=15.4A; DSC6: Ppp=400W; ID: 4; Manufacture: 硕凯; Part Name: TVS; Part Number: C040602260004
F2 = FUSE-SMD1812: DSC1: 16V; DSC2: 2.6A; DSC3: SCF260-16-1812RB; ID: 7; Manufacture: 硕凯; Part Name: 自恢复保险丝; Part Number: C160102670007; Price: 0.3
Hole1-Hole4 = MH-NOE: DSC1: 顶层和底层焊盘直径=6mm; DSC2: 孔径3.7mm; DSC3: 8个过孔; ID: 33; Part Name: 镀锡(金)焊盘固定孔
J1 = J-DC-044A-2_5: DSC1: 通孔弯针，内径2mm，2.5A，24VDC; DSC2: 11.5*10.1*7.3mm; DSC3: 通孔弯针; DSC4: DC-044A-2.5A-2.0(星坤); DSC5: DC0044A（九龙熹）; ID: 3; Part Name: DC座; Part Number: J100103010003
J7-J9 J32 = J-H-4P: DSC1: 4p; DSC2: 2.0mm间距; DSC3: 通孔180度直针; DSC4: 米黄色胶壳 耐高温; DSC5: JLX-PH20-4A（九龙熹）; DSC6: X2016WV-04-46SN(星坤); ID: 13; Part Name: PH; Part Number: J020302820003
L1 = L-CMLP: DSC2: 600Ω@100MHz; DSC3: 2.5A; DSC5: -40℃ ~ +85℃; DSC6: SMD_4P,4.5x3.2x2.8 mm; ID: 10; Manufacture: 宗成; Part Name: 电源共模电感; Price: 3.25
L2 L3 = L-IND: DSC1: ±20%; DSC2: Isat=6.1A; DSC3: Irms=4.3A; DSC4: 48mΩ; DSC5: 4.0*4.0*2.0mm; DSC6: WPN4020H2R2MT(顺络); DSC7: FHD4020S-2R2MT(长江微电); DSC8: ZCRH4020-2.2uH-M(宗成); ERP Number: 1010200404; ID: 20; Manufacture: 宗成|长江微电|顺络; Part Name: 功率电感; Part Number: C060202340020; Price: 0.38
L4 = L-IND: DSC1: ±20%; DSC2: Isat=3.6A; DSC3: Irms=3A; DSC4: 54mΩ; DSC5: 2.5*2.0*1.2mm; DSC6: WPN252012H1R0MT(顺络); DSC7: FHD252012S-1R0MT(长江微电); DSC8: ZCRH252012-1uH-M(宗成); ID: 52; Manufacture: 宗成|长江微电|顺络; Part Name: 功率电感
LED1 = D-LED-DIP-2: DSC1: 双孔座2位黑色方形灯柱 90度弯脚 左正右负 上红下绿; ID: 22; Part Name: LED; Part Number: C140202660018
MARK1 MARK2 MARK4 = MARK-FID10X20_1: ID: 9; Part Name: 光学MARK点
MARK3 = MARK-FID10X20_0: ID: 9; Part Name: 光学MARK点
R1 R2 R17 = R-0805: DSC1: ±1%; DSC2: 1/8W; ERP Number: 1010200199; ID: 1,448; Part Name: 贴片电阻; Part Number: C011002081448; Price: 0.01
R3 R30 = R-0402: DSC1: ±5%; DSC2: 1/16W; ERP Number: 1010200103; ID: 353; Part Name: 贴片电阻; Part Number: C011002080353; Price: 0.01
R4 R11 = R-0402: DSC1: ±1%; DSC2: 1/16W; ID: 978; Part Name: 贴片电阻; Part Number: C011002080978; Price: 0.01
R5 R7 R74 = R-0402: DSC1: ±5%; DSC2: 1/16W; ERP Number: 1010200182; ID: 345; Part Name: 贴片电阻; Part Number: C011002080345; Price: 0.01
R6 R12 = R-0402: DSC1: ±1%; DSC2: 1/16W; ERP Number: 1010200333; ID: 889; Part Name: 贴片电阻; Part Number: C011002080889; Price: 0.01
R8 R10 R13 R14 = R-0402: DSC1: ±5%; DSC2: 1/16W; ERP Number: 1010200104; ID: 303; Part Name: 贴片电阻; Part Number: C011002080303; Price: 0.01
R9 R28 = R-0402: DSC1: ±5%; DSC2: 1/16W; ERP Number: 1010200258; ID: 332; Part Name: 贴片电阻; Part Number: C011002080332; Price: 0.01
R15 = R-0402: DSC1: ±1%; DSC2: 1/16W; ID: 932; Part Name: 贴片电阻; Part Number: C011002080932; Price: 0.01
R16 R66 = R-0402: DSC1: ±1%; DSC2: 1/16W; ERP Number: 1010200140; ID: 856; Part Name: 贴片电阻; Part Number: C011002080856; Price: 0.01
U1 U2 = U-ETA1654FSG: DSC1: Vi=4.5-17V; DSC2: Vo=0.805-13.5V; DSC3: Io=4A; DSC4: Vfb=0.805V; DSC5: 0.97; DSC6: 600KHz; DSC7: 同步降压; ID: 44; Manufacture: ETA; Part Name: DCDC; Part Number: C070209233998; Solder: 量产
U3 = U-ETA3417S2F: DSC1: Vi=2.6-7.0V; DSC2: Vo=0.6-7.0V; DSC3: Io=2.5A; DSC4: Vfb=0.6V; DSC6: 3MHz; DSC7: 同步降压; DSC8: 替代料：TI的TLV62569DBVR/矽力杰SY8089AAAC; ID: 43; Manufacture: ETA; Part Name: DCDC; Part Number: C070205183984; Solder: 量产
J2 = ATMD097-AED4S-5F_5
D2 D5-D10 D12 D15 D16 D18-D26 = DI-ESD: DSC1: 双向; DSC2: Vdc=12V; DSC4: Vc=40V; DSC5: Cj=0.05pF; ID: 1; Manufacture: 硕凯; Part Name: ESD; Part Number: C040504013980; Price: 0.06; Solder: 推荐
D3 D4 D14 D17 D107 = DI-ESD-SE05NRC14GA: DSC1: 双向; DSC2: Vdc=5V; DSC3: Vbr=8V; DSC4: Vc=20V; DSC5: Cj=0.4pF; ID: 8; Manufacture: 硕凯; Part Name: ESD; Part Number: C040504013981; Price: 0.15; Solder: 推荐
J3 = J-TF-01A: DSC1: 自弹式 MicroSD卡(TF卡) 卡座 外焊 外扣,无弹片 本体最大高度：2mm; DSC3: 贴片; DSC4: KLM-1007（九龙熹）; DSC5: XKTF-N02-N(星坤); ID: 2; Part Name: SD卡座; Part Number: J080102980002
J4 = J-A-3P: DSC1: 3p; DSC2: 1.25mm间距; DSC3: 立贴; DSC4: 米黄色胶壳 耐高温; DSC5: JLX-1.25T-3AB(九龙熹); DSC6: X9821WVS-03-9TSN(星坤); ID: 7; Part Name: MX1.25T; Part Number: J020102800059
R18-R24 = R-0402: DSC1: ±5%; DSC2: 1/16W; ERP Number: 1010200173; Part Name: 贴片电阻; Part Number: C011002080262; Price: 0.01
R25 R26 = R-0402: DSC1: ±1%; DSC2: 1/16W; ERP Number: 1010200450; ID: 630; Part Name: 贴片电阻; Part Number: C011002080630; Price: 0.01
C39 C41 C55-C62 C290 C291 = C-0402: DSC1: ±10%; DSC2: 10V; DSC3: X7R; ID: 60; Manufacture: 三星|国巨|村田; Part Name: 贴片电容; Part Number: C020102120060; Price: 0.01
C49 C51 = C-0402: DSC1: ±5%; DSC2: 50V; DSC3: C0G; ERP Number: 1010200091; ID: 27; Manufacture: 三星|国巨|村田; Part Name: 贴片电容; Part Number: C020102120027; Price: 0.02
D11 D13 = DI-XI-S: DSC1: VR=40V; DSC2: IF=1A; DSC3: VF=600mV/1A; DSC4: IR=1mA; ID: 5; Manufacture: 长电; Part Name: 肖特基二级管; Part Number: C040202220005; Price: 0.13
J5 = J-TYPE_C_16P: DSC1: TYPE-C，16Pin母座，卧贴，无卷边，耐高温; DSC2: 8.6*2.5mm; DSC3: 卧贴; DSC4: U262-161N-4BVC11（星坤）; DSC5: TYPE-CF-16P-RAT-L7.3（九龙熹）; ID: 11; Part Name: USB连接器; Part Number: J060111203952
J6 = J-USB-9AFx2-DIP-W: DSC1: USB-3.0，插件弯脚，双层，蓝胶，有卷边，耐高温; DSC2: 17.5*14.5*15.5mm; DSC3: 通孔弯针; DSC5: JLX-USB-030（九龙熹）; ID: 14; Part Name: USB连接器; Part Number: J060111093946
L5-L10 = L-CMLS-ACM2012: DSC1: 90uH@100kHz; DSC2: 90Ω@100MHz; DSC3: 400mA; DSC4: DCR=300mΩ; DSC5: -40℃ ~ +125℃; DSC6: SMD_4P,2x1.2mm; ERP Number: 1010200196; ID: 1; Manufacture: 台庆; Part Name: 信号共模电感; Part Number: C060402360001; Price: 0.13
Q1 Q2 = N-MOS-Q: DSC1: Vds=30V; DSC2: Id=100mA; DSC3: Vgs(th)=1.5V; DSC4: Vgs=±20V; DSC5: pd=150mW; ERP Number: 1010800011; ID: 4; Manufacture: 先科; Part Name: N-MOS; Part Number: C030202190004; Price: 0.1
R27 R54 R55 R58 R59 R65 = R-0402: DSC1: ±5%; DSC2: 1/16W; ERP Number: 1010200096; ID: 328; Part Name: 贴片电阻; Part Number: C011002080328; Price: 0.01
R29 R34 R42 R43 R46-R49 R52 R56 R64 R67 R75 R78 R375 R376 = R-0402: DSC1: ±5%; DSC2: 1/16W; ERP Number: 1010200263; ID: 238; Part Name: 贴片电阻; Part Number: C011002080238; Price: 0.01
R31 R35 R38 R40 R53 R61 R69 R71 R76 = R-0402: DSC1: ±5%; DSC2: 1/16W; ERP Number: 1010200100; ID: 217; Part Name: 贴片电阻; Part Number: C011002080217; Price: 0.01
R32 R57 R70 R77 = R-0402: DSC1: ±5%; DSC2: 1/16W; ERP Number: 1010200173; ID: 262; Part Name: 贴片电阻; Part Number: C011002080262; Price: 0.01
R33 R45 R51 R60 R72 R79 = R-0402: DSC1: ±5%; DSC2: 1/16W; ID: 324; Part Name: 贴片电阻; Part Number: C011002080324; Price: 0.01
R36 = R-0402: DSC1: ±5%; DSC2: 1/16W; ID: 371; Part Name: 贴片电阻; Part Number: C011002080371; Price: 0.01
R37 = R-0402: DSC1: ±5%; DSC2: 1/16W; ID: 349; Part Name: 贴片电阻; Part Number: C011002080349; Price: 0.01
R39 = R-0402: DSC1: ±5%; DSC2: 1/16W; ERP Number: 1010200469; ID: 341; Part Name: 贴片电阻; Part Number: C011002080341; Price: 0.01
R41 = R-0402: DSC1: ±5%; DSC2: 1/16W; ID: 362; Part Name: 贴片电阻; Part Number: C011002080362; Price: 0.01
R68 = R-0402: DSC1: ±5%; DSC2: 1/16W; ERP Number: 1010200167; ID: 378; Part Name: 贴片电阻; Part Number: C011002080378; Price: 0.01
R73 = R-0402: DSC1: ±1%; DSC2: 1/16W; ID: 789; Part Name: 贴片电阻; Part Number: C011002080789; Price: 0.01
U4-U7 U9 U10 = U-SY6280AAC_1: DSC1: 低能耗电源开关; DSC2: 2.4-5.5V 2A; DSC3: 80m?; DSC4: -40~85℃; ERP Number: 1010100222; ID: 1; Manufacture: 矽力杰; Part Name: 功率开关; Part Number: C070402430001; Price: 0.42
U8 = U-FE2_0.1: DSC1: USB 2.0 HIGH SPEED 7-PORT HUB CONTROLLER; DSC2: 48 PIN LQFP - 7mmX7mm,0.5 Pitch; ID: 21; Manufacture: TERMINUS; Part Name: USB芯片; Part Number: C100202500010
XT1 = XTAL-4P: DSC1: 100Ω; DSC2: ±10ppm; DSC3: 12pF; DSC4: -40℃~+85℃; DSC5: 3.2*2.5mm 4P; ERP Number: 1010700002; ID: 4; Manufacture: 泰晶; Part Name: 贴片无源晶振; Part Number: C050102290004; Price: 0.45

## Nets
GND: C3.2 C4.1 C5.1 C6.1 C7.1 C9.1 C10.1 C11.1 C12.1 C14.1 C15.1 C16.1 C18.1 C19.1 C20.1 C21.1 C22.1 C23.1 C25.1 C26.1 C27.1 C28.1 C29.1 C30.1 C31.1 C32.1 C33.2 C34.2 C35.1 C36.2 C37.2 C38.2 C40.2 C42.2 C43.2 C44.1 C45.1 C46.2 C47.2 C48.1 C49.1 C50.1 C51.1 C52.2 C53.2 C54.1 C55.1 C56.1 C57.1 C58.1 C59.1 C60.1 C61.1 C62.1 D2.1(I/O2) D3.3 D3.8 D4.3 D4.8 D5.1(I/O2) D6.1(I/O2) D7.1(I/O2) D8.1(I/O2) D9.1(I/O2) D10.1(I/O2) D12.1(I/O2) D14.3 D14.8 D15.2(I/O1) D16.2(I/O1) D17.3 D17.8 D18.1(I/O2) D19.1(I/O2) D20.1(I/O2) D21.1(I/O2) D22.1(I/O2) D23.1(I/O2) D24.1(I/O2) D25.1(I/O2) D26.1(I/O2) D107.3 D107.8 J2.15(GND1) J2.30(GND2) J2.31(GND3) J2.51(GND4) J2.56(GND5) J2.69(GND6) J2.84(GND7) J2.95(GND8) J2.106(GND9) J2.121(GND10) J2.145(GND11) J2.151(GND12) J2.158(GND13) J2.165(GND14) J2.180(GND15) J2.194(GND16) J2.195(GND17) J2.214(GND18) J2.217(GND19) J2.240(GND20) J2.254(GND21) J2.256(GND22) J2.258(GND23) J2.260(GND24) J2.N1 J2.N2 J2.N3 J2.N4 J3.6(VSS) J3.10(G1) J3.11(G2) J3.12(G3) J3.13(G4) J4.3 J4.4 J4.5 J5.A1(GND1) J5.A12(GND2) J5.B1(GND3) J5.B12(GND4) J5.H1(GND5) J5.H2(GND6) J5.H3(GND7) J5.H4(GND8) J6.4(GND1) J6.7(GND2) J6.13(GND3) J6.16(GND4) J6.19(SHELL1) J6.20(SHELL2) J6.21(SHELL3) J6.22(SHELL4) J7.4 J8.4 J9.4 L1.3 LED1.2 LED1.4 Q1.2(SOURCE) Q2.2(SOURCE) R2.2 R5.1 R6.1 R9.1 R12.1 R16.1 R28.1 R33.1 R36.1 R41.1 R45.1 R51.1 R60.1 R72.1 R73.2 R79.1 U1.3(GND) U2.3(GND) U3.2(GND) U4.2(GND) U5.2(GND) U6.2(GND) U7.2(GND) U8.6(VSS) U8.10(VS_PLL) U8.16(VSS_1) U8.22(VSS-2) U8.25(VS_A) U8.33(VSS_3) U8.37(DIS_REG) U8.40(TEST) U9.2(GND) U10.2(GND) XT1.2 XT1.4 ; also on sheet 8 9 10 11 12 13 14 15 16 17 18 19 20
GND_EARTH: Hole1.1 Hole2.1 Hole3.1 Hole4.1 ; also on sheet 13 14
GND_IN: C2.1 D1.C(I/O1) J1.2 J1.3 J32.1 J32.2 L1.2 R2.1 ; also on sheet 11 17
VBUSM: R74.1 U8.35(VBUSM)
VCC3V3_SD: C31.2 D2.2(I/O1) J2.210(VCC3V3_SD_OUT) J3.4(VDD)
VCC5V0_M: C26.2 C27.2 C28.2 C29.2 J2.253(VCC5V0_SYS1) J2.255(VCC5V0_SYS2) J2.257(VCC5V0_SYS3) J2.259(VCC5V0_SYS4) R17.2
VCC5V0_USB1: C42.1 D19.2(I/O1) J7.1 U7.1(VOUT)
VCC5V0_USB2: C46.1 D21.2(I/O1) J8.1 U9.1(VOUT)
VCC5V0_USB3: C52.1 D24.2(I/O1) J9.1 U10.1(VOUT)
VCC5V0_USB_HOST1: C38.1 D16.1(I/O2) J6.10(VBUS2) U6.1(VOUT)
VCC5V0_USB_HOST2: C36.1 D15.1(I/O2) J6.1(VBUS1) U5.1(VOUT)
VCC5V0_USB_OTG0: C32.2 C34.1 D7.2(I/O1) J5.A4(VBUS_1) J5.A9(VBUS_2) J5.B4(VBUS_3) J5.B9(VBUS_4) R27.1 U4.1(VOUT)
VCC5V_SYS: C8.2 C9.2 C10.2 C11.2 L2.2 R4.2 R7.2 R17.1 ; also on sheet 10
VCC12V_DCIN: F2.1 J1.4 J32.3 J32.4 ; also on sheet 11 17
VCC_1V8: J2.237(VCC_1V8_OUT) R30.2 ; also on sheet 9 11 12 13 14 15 20
VCC_1V8_HUB: C50.2 C60.2 C61.2 C62.2 U8.3(VD18_1) U8.9(VD_PLL) U8.26(VREG18) U8.29(VD18)
VCC_3V3: J2.245(VCC_3V3_OUT) R14.1
VCC_3V3_HUB: C54.2 C55.2 C56.2 C57.2 C58.2 C59.2 R54.2 R55.2 R58.2 R59.1 R61.2 R65.1 R66.2 R76.2 U8.13(VDD33_1) U8.19(VDD33_2) U8.27(VD3_IN) U8.32(VDD33_3) U8.41(VDD33_4)
VCC_5V: C17.2 C18.2 C19.2 C20.2 C22.2 C23.2 C33.1 C37.1 C40.1 C43.1 C47.1 C53.1 L3.2 R11.2 U3.4(VIN) U4.5(IN) U5.5(IN) U6.5(IN) U7.5(IN) U9.5(IN) U10.5(IN) ; also on sheet 8 9 11 15 17 18
VCC_12V: C3.1 C4.2 C5.2 C6.2 C7.2 C14.2 C15.2 C16.2 L1.4 R1.2 R3.2 U1.1(IN) U2.1(IN)
VDD_3V3: C21.2 C24.2 C25.2 L4.2 R10.1 R15.2 R37.2 R74.2 R76.1 ; also on sheet 8 9 10 11 12 13 14 15 16 17 19 20
4G_PWREN_H_GPIO0_D5: J2.11(GPIO0_D5_d/SARADC_VIN6) ; also on sheet 18
4G_RESET_L_GPIO0_D4: J2.9(GPIO0_D4_d/SARADC_VIN5) ; also on sheet 18
BT_REG_ON_H_GPIO1_D4: J2.18(FSPI_D3/FLASH_CS1n/GPIO1_D4_u) ; also on sheet 20
BT_WAKE_HOST_H_GPIO2_C1: J2.228(I2S2_MCLK_M0/ETH0_REFCLKO_25M/UART7_RTSn_M0/SPI2_CLK_M0/GPIO2_C1_d) ; also on sheet 20
CAM0_PDN_H_GPIO1_D0: J2.10(FSPI_CLK/FLASH_ALE/GPIO1_D0_d) ; also on sheet 12
CAM0_RST_L__GPIO1_D1: J2.12(FSPI_D0/FLASH_RDY/GPIO1_D1_u) ; also on sheet 12
CAM1_PDN_H_GPIO1_D2: J2.14(FSPI_D1/FLASH_RDn/GPIO1_D2_u) ; also on sheet 12
CAM1_RST_L_GPIO1_C7: J2.16(FSPI_D2/FLASH_WPn/GPIO1_C7_d) ; also on sheet 12
CAM_CLKOUT0: J2.108(REFCLK_OUT/GPIO0_A0_d) ; also on sheet 12
CAMERA_PWREN_GPIO4_D2: J2.13(GPIO4_D2_d/SARADC_VIN7) ; also on sheet 12
CAN1_RX_M0: J2.154(I2C3_SDA_M0/UART3_RX_M0/CAN1_RX_M0/AUDIOPWM_LOUT_P/ACODEC_ADC_DATA/GPIO1_A0_u) ; also on sheet 15
CAN1_TX_M0: J2.156(I2C3_SCL_M0/UART3_TX_M0/CAN1_TX_M0/AUDIOPWM_LOUT_N/ACODEC_ADC_CLK/GPIO1_A1_u) ; also on sheet 15
CAN2_RX_M0: J2.44(I2C2_SDA_M1/EBC_GDSP/CAN2_RX_M0/ISP_FLASH_TRIGIN/VOP_BT656_CLK_M1/GPIO4_B4_d) ; also on sheet 15
CAN2_TX_M0: J2.46(I2C2_SCL_M1/EBC_SDSHR/CAN2_TX_M0/I2S1_SDO3_M1/GPIO4_B5_d) ; also on sheet 15
CIF_CLKOUT_SOC: J2.52(CIF_CLKOUT/EBC_GDCLK/PWM11_IR_M1/GPIO4_C0_d) ; also on sheet 12
CLK_32K_OUT_GPIO0_B0: J2.112(CLK32K_IN/CLK32K_OUT0/PCIE30X2_BUTTONRSTn/GPIO0_B0_u) ; also on sheet 16
DM1_: D18.2(I/O1) J7.2 L8.3 R52.2
DM2_: D23.2(I/O1) J8.2 L9.3 R64.2
DM3_: D25.2(I/O1) J9.2 L10.3 R75.2
DP1_: D20.2(I/O1) J7.3 L8.4 R56.2
DP2_: D22.2(I/O1) J8.3 L9.4 R67.2
DP3_: D26.2(I/O1) J9.3 L10.4 R78.2
DRV: U8.42(DRV)
EDP_EN_H_GPIO0_C5: J2.130(PWM6/SPI0_MISO_M0/PCIE30X2_WAKEn_M0/GPIO0_C5_d) ; also on sheet 17
EDP_ON_GPIO0_C3: J2.126(PWM4/VOP_PWM_M0/PCIE30X1_PERSTn_M0/MCU_JTAG_TRSTn/GPIO0_C3_d) ; also on sheet 17
EDP_PWM7: J2.132(PWM7_IR/SPI0_CS0_M0/PCIE30X2_PERSTn_M0/GPIO0_C6_d) ; also on sheet 17
EDP_TX_AUXN: J2.197(EDP_TX_AUXN) ; also on sheet 17
EDP_TX_AUXP: J2.199(EDP_TX_AUXP) ; also on sheet 17
EDP_TX_D0N: J2.213(EDP_TX_D0N) ; also on sheet 17
EDP_TX_D0P: J2.215(EDP_TX_D0P) ; also on sheet 17
EDP_TX_D1N: J2.209(EDP_TX_D1N) ; also on sheet 17
EDP_TX_D1P: J2.211(EDP_TX_D1P) ; also on sheet 17
EDP_TX_D2N: J2.205(EDP_TX_D2N) ; also on sheet 17
EDP_TX_D2P: J2.207(EDP_TX_D2P) ; also on sheet 17
EDP_TX_D3N: J2.201(EDP_TX_D3N) ; also on sheet 17
EDP_TX_D3P: J2.203(EDP_TX_D3P) ; also on sheet 17
EXT_EN: J2.249(EXT_EN) R13.1
FE1_1_DM0: R71.1 U8.30(DMU)
FE1_1_DM1: L8.2 R52.1 U8.23(DM1) ; also on sheet 15
FE1_1_DM2: L9.2 R64.1 U8.20(DM2)
FE1_1_DM3: L10.2 R75.1 U8.17(DM3)
FE1_1_DM4: U8.14(DM4) ; also on sheet 18
FE1_1_DP0: R69.1 U8.31(DPU)
FE1_1_DP1: L8.1 R56.1 U8.24(DP1) ; also on sheet 15
FE1_1_DP2: L9.1 R67.1 U8.21(DP2)
FE1_1_DP3: L10.1 R78.1 U8.18(DP3)
FE1_1_DP4: U8.15(DP4) ; also on sheet 18
FE1_1_XIN: C49.2 R68.1 U8.12(XIN) XT1.1
FE1_1_XOUT: C51.2 R68.2 U8.11(XOUT) XT1.3
GMAC0_MCLKINOUT: J2.230(I2S2_SCLK_TX_M0/GMAC0_MCLKINOUT/UART7_CTSn_M0/SPI2_MISO_M0/GPIO2_C2_d) ; also on sheet 13
GMAC0_MDC: J2.232(I2S2_LRCK_TX_M0/GMAC0_MDC/UART9_RTSn_M0/SPI2_MOSI_M0/GPIO2_C3_d) ; also on sheet 13
GMAC0_MDIO: J2.234(I2S2_SDO_M0/GMAC0_MDIO/UART9_CTSn_M0/SPI2_CS0_M0/GPIO2_C4_d) ; also on sheet 13
GMAC0_RSTn_GPIO2_D5: J2.77(LCDC_D5/VOP_BT656_D5_M0/SPI2_CS0_M1/PCIE30X2_WAKEn_M1/I2S1_SDI2_M2/GPIO2_D5_d) ; also on sheet 13
GMAC0_RXCLK: J2.223(SDMMC1_D2/GMAC0_RXCLK/UART7_RX_M0/GPIO2_A5_u) ; also on sheet 13
GMAC0_RXD0: J2.222(GMAC0_RXD0/UART1_CTSn_M0/SPI1_MISO_M0/GPIO2_B6_u) ; also on sheet 13
GMAC0_RXD1: J2.224(I2S2_SCLK_RX_M0/GMAC0_RXD1/UART6_RTSn_M0/SPI1_MOSI_M0/GPIO2_B7_d) ; also on sheet 13
GMAC0_RXD2: J2.219(SDMMC1_D0/GMAC0_RXD2/UART6_RX_M0/GPIO2_A3_u) ; also on sheet 13
GMAC0_RXD3: J2.221(SDMMC1_D1/GMAC0_RXD3/UART6_TX_M0/GPIO2_A4_u) ; also on sheet 13
GMAC0_RXDV_CRS: J2.226(I2S2_LRCK_RX_M0/GMAC0_RXDV_CRS/UART6_CTSn_M0/SPI1_CS0_M0/GPIO2_C0_d) ; also on sheet 13
GMAC0_TXCLK: J2.229(SDMMC1_CLK/GMAC0_TXCLK/UART9_TX_M0/GPIO2_B0_d) ; also on sheet 13
GMAC0_TXD0: J2.216(GMAC0_TXD0/UART1_RX_M0/GPIO2_B3_u) ; also on sheet 13
GMAC0_TXD1: J2.218(GMAC0_TXD1/UART1_TX_M0/GPIO2_B4_u) ; also on sheet 13
GMAC0_TXD2: J2.225(SDMMC1_D3/GMAC0_TXD2/UART7_TX_M0/GPIO2_A6_u) ; also on sheet 13
GMAC0_TXD3: J2.227(SDMMC1_CMD/GMAC0_TXD3/UART9_RX_M0/GPIO2_A7_u) ; also on sheet 13
GMAC0_TXEN: J2.220(GMAC0_TXEN/UART1_RTSn_M0/SPI1_CLK_M0/GPIO2_B5_u) ; also on sheet 13
GMAC1_MCLKINOUT_M1: J2.54(CIF_CLKIN/EBC_SDCLK/GMAC1_MCLKINOUT_M1/UART1_CTSn_M1/I2S2_SCLK_RX_M1/GPIO4_C1_d) ; also on sheet 14
GMAC1_MDC_M1: J2.48(CIF_HREF/EBC_SDLE/GMAC1_MDC_M1/UART1_RTSn_M1/I2S2_MCLK_M1/GPIO4_B6_d) ; also on sheet 14
GMAC1_MDIO_M1: J2.50(CIF_VSYNC/EBC_SDOE/GMAC1_MDIO_M1/I2S2_SCLK_TX_M1/GPIO4_B7_d) ; also on sheet 14
GMAC1_RSTn_GPIO2_D7: J2.73(LCDC_D7/VOP_BT656_D7_M0/SPI2_MISO_M1/UART8_TX_M1/I2S1_SDO0_M2/GPIO2_D7_d) ; also on sheet 14
GMAC1_RXCLK_M1: J2.45(CIF_D13/EBC_SDDO13/GMAC1_RXCLK_M1/UART7_RX_M2/PDM_SDI3_M1/GPIO4_A3_d) ; also on sheet 14
GMAC1_RXD0_M1: J2.34(CAM_CLKOUT0/EBC_SDCE1/GMAC1_RXD0_M1/SPI3_CS1_M0/I2S1_LRCK_RX_M1/GPIO4_A7_d) ; also on sheet 14
GMAC1_RXD1_M1: J2.36(CAM_CLKOUT1/EBC_SDCE2/GMAC1_RXD1_M1/SPI3_MISO_M0/I2S1_SDO1_M1/GPIO4_B0_d) ; also on sheet 14
GMAC1_RXD2_M1: J2.41(CIF_D11/EBC_SDDO11/GMAC1_RXD2_M1/PDM_SDI1_M1/GPIO4_A1_d) ; also on sheet 14
GMAC1_RXD3_M1: J2.43(CIF_D12/EBC_SDDO12/GMAC1_RXD3_M1/UART7_TX_M2/PDM_SDI2_M1/GPIO4_A2_d) ; also on sheet 14
GMAC1_RXDV_CRS_M1: J2.38(ISP_PRELIGHT_TRIG/EBC_SDCE3/GMAC1_RXDV_CRS_M1/I2S1_SDO2_M1/GPIO4_B1_d) ; also on sheet 14
GMAC1_TXCLK_M1: J2.39(CIF_D10/EBC_SDDO10/GMAC1_TXCLK_M1/PDM_CLK1_M1/GPIO4_A0_d) ; also on sheet 14
GMAC1_TXD0_M1: J2.47(CIF_D14/EBC_SDDO14/GMAC1_TXD0_M1/UART9_TX_M2/I2S2_LRCK_TX_M1/GPIO4_A4_d) ; also on sheet 14
GMAC1_TXD1_M1: J2.49(CIF_D15/EBC_SDDO15/GMAC1_TXD1_M1/UART9_RX_M2/I2S2_LRCK_RX_M1/GPIO4_A5_d) ; also on sheet 14
GMAC1_TXD2_M1: J2.35(CIF_D8/EBC_SDDO8/GMAC1_TXD2_M1/UART1_TX_M1/PDM_CLK0_M1/GPIO3_D6_d) ; also on sheet 14
GMAC1_TXD3_M1: J2.37(CIF_D9/EBC_SDDO9/GMAC1_TXD3_M1/UART1_RX_M1/PDM_SDI0_M1/GPIO3_D7_d) ; also on sheet 14
GMAC1_TXEN_M1: J2.32(ISP_FLASHTRIGOUT/EBC_SDCE0/GMAC1_TXEN_M1/SPI3_CS0_M0/I2S1_SCLK_RX_M1/GPIO4_A6_d) ; also on sheet 14
HDMI_TX_CLKN: J2.147(HDMI_TX_CLKN) ; also on sheet 10
HDMI_TX_CLKP: J2.149(HDMI_TX_CLKP) ; also on sheet 10
HDMI_TX_D0N: J2.155(HDMI_TX_D0N) ; also on sheet 10
HDMI_TX_D0P: J2.153(HDMI_TX_D0P) ; also on sheet 10
HDMI_TX_D1N: J2.159(HDMI_TX_D1N) ; also on sheet 10
HDMI_TX_D1P: J2.157(HDMI_TX_D1P) ; also on sheet 10
HDMI_TX_D2N: J2.163(HDMI_TX_D2N) ; also on sheet 10
HDMI_TX_D2P: J2.161(HDMI_TX_D2P) ; also on sheet 10
HDMI_TX_HPDIN: J2.143(HDMI_TX_HPDIN) ; also on sheet 10
HDMITX_CEC_M0: J2.89(HDMITX_CEC_M0/SPI3_CS1_M1/GPIO4_D1_u) ; also on sheet 10
HOST_WAKE_BT_H_GPIO1_D3: J2.20(FSPI_CS0n/FLASH_CS0n/GPIO1_D3_u) ; also on sheet 20
HP_SNS: J2.244(HP_SNS) ; also on sheet 8
HPL_OUT: J2.242(HPL_OUT) ; also on sheet 8
HPR_OUT: J2.246(HPR_OUT) ; also on sheet 8
HUB_RST: C48.2 R53.2 R66.1 U8.34(XRSTJ)
HUB_RST_GPIO1_A4_d: J2.8(I2S1_SCLK_RX_M0/UART4_RX_M0/PDM_CLK1_M0/SPDIF_TX_M0/GPIO1_A4_d) R53.1
I2C1_SCL: J2.146(I2C1_SCL/CAN0_TX_M0/PCIE30X1_BUTTONRSTn/MCU_JTAG_TDO/GPIO0_B3_u) ; also on sheet 15
I2C1_SDA: J2.148(I2C1_SDA/CAN0_RX_M0/PCIE20_BUTTONRSTn/MCU_JTAG_TCK/GPIO0_B4_u) ; also on sheet 15
I2C2_SCL_M0: J2.150(I2C2_SCL_M0/SPI0_CLK_M0/PCIE20_WAKEn_M0/PWM1_M1/GPIO0_B5_u) ; also on sheet 11
I2C2_SDA_M0: J2.152(I2C2_SDA_M0/SPI0_MOSI_M0/PCIE20_PERSTn_M0/PWM2_M1/GPIO0_B6_u) ; also on sheet 11
I2C3_SCL_M1: J2.74(LCDC_D20/VOP_BT1120_D11/GMAC1_TXD0_M0/I2C3_SCL_M1/PWM10_M0/GPIO3_B5_d) ; also on sheet 9
I2C3_SDA_M1: J2.72(LCDC_D21/VOP_BT1120_D12/GMAC1_TXD1_M0/I2C3_SDA_M1/PWM11_IR_M0/GPIO3_B6_d) ; also on sheet 9
I2C4_SCL_M0: J2.42(I2C4_SCL_M0/EBC_GDOE/ETH1_REFCLKO_25M_M1/SPI3_CLK_M0/I2S2_SDO_M1/GPIO4_B3_d) ; also on sheet 12
I2C4_SDA_M0: J2.40(I2C4_SDA_M0/EBC_VCOM/GMAC1_RXER_M1/SPI3_MOSI_M0/I2S2_SDI_M1/GPIO4_B2_d) ; also on sheet 12
I2C5_SCL-HDMI: J2.93(HDMITX_SCL/I2C5_SCL_M1/GPIO4_C7_u) ; also on sheet 10
I2C5_SCL_M0: J2.78(LCDC_D18/VOP_BT1120_D9/GMAC1_RXDV_CRS_M0/I2C5_SCL_M0/PDM_SDI0_M2/GPIO3_B3_d) ; also on sheet 12 19
I2C5_SDA-HDMI: J2.91(HDMITX_SDA/I2C5_SDA_M1/GPIO4_D0_u) ; also on sheet 10
I2C5_SDA_M0: J2.76(LCDC_D19/VOP_BT1120_D10/GMAC1_RXER_M0/I2C5_SDA_M0/PDM_SDI1_M2/GPIO3_B4_d) ; also on sheet 12 19
LVDS_EN_GPIO3_A2: J2.65(LCDC_D9/VOP_BT1120_D1/GMAC1_TXD2_M0/I2S3_MCLK_M0/SDMMC2_D1_M1/GPIO3_A2_d) ; also on sheet 11
LVDS_ON_GPIO3_A1: J2.67(LCDC_D8/VOP_BT1120_D0/SPI1_CS0_M1/PCIE30X1_PERSTn_M1/SDMMC2_D0_M1/GPIO3_A1_d) ; also on sheet 11
MIC1_INN: J2.250(MIC1_INN) ; also on sheet 8
MIC1_INP: J2.248(MIC1_INP) ; also on sheet 8
MIPI_CSI_RX_CLK0N: J2.103(MIPI_CSI_RX_CLK0N) ; also on sheet 12
MIPI_CSI_RX_CLK0P: J2.101(MIPI_CSI_RX_CLK0P) ; also on sheet 12
MIPI_CSI_RX_CLK1N: J2.99(MIPI_CSI_RX_CLK1N) ; also on sheet 12
MIPI_CSI_RX_CLK1P: J2.97(MIPI_CSI_RX_CLK1P) ; also on sheet 12
MIPI_CSI_RX_D0N: J2.119(MIPI_CSI_RX_D0N) ; also on sheet 12
MIPI_CSI_RX_D0P: J2.117(MIPI_CSI_RX_D0P) ; also on sheet 12
MIPI_CSI_RX_D1N: J2.115(MIPI_CSI_RX_D1N) ; also on sheet 12
MIPI_CSI_RX_D1P: J2.113(MIPI_CSI_RX_D1P) ; also on sheet 12
MIPI_CSI_RX_D2N: J2.111(MIPI_CSI_RX_D2N) ; also on sheet 12
MIPI_CSI_RX_D2P: J2.109(MIPI_CSI_RX_D2P) ; also on sheet 12
MIPI_CSI_RX_D3N: J2.107(MIPI_CSI_RX_D3N) ; also on sheet 12
MIPI_CSI_RX_D3P: J2.105(MIPI_CSI_RX_D3P) ; also on sheet 12
MIPI_DSI_TX0_CLKN: J2.133(MIPI_DSI_TX0_CLKN/LVDS_TX0_CLKN) ; also on sheet 11
MIPI_DSI_TX0_CLKP: J2.131(MIPI_DSI_TX0_CLKP/LVDS_TX0_CLKP) ; also on sheet 11
MIPI_DSI_TX0_D0N: J2.141(MIPI_DSI_TX0_D0N/LVDS_TX0_D0N) ; also on sheet 11
MIPI_DSI_TX0_D0P: J2.139(MIPI_DSI_TX0_D0P/LVDS_TX0_D0P) ; also on sheet 11
MIPI_DSI_TX0_D1N: J2.137(MIPI_DSI_TX0_D1N/LVDS_TX0_D1N) ; also on sheet 11
MIPI_DSI_TX0_D1P: J2.135(MIPI_DSI_TX0_D1P/LVDS_TX0_D1P) ; also on sheet 11
MIPI_DSI_TX0_D2N: J2.129(MIPI_DSI_TX0_D2N/LVDS_TX0_D2N) ; also on sheet 11
MIPI_DSI_TX0_D2P: J2.127(MIPI_DSI_TX0_D2P/LVDS_TX0_D2P) ; also on sheet 11
MIPI_DSI_TX0_D3N: J2.125(MIPI_DSI_TX0_D3N/LVDS_TX0_D3N) ; also on sheet 11
MIPI_DSI_TX0_D3P: J2.123(MIPI_DSI_TX0_D3P/LVDS_TX0_D3P) ; also on sheet 11
MIPI_DSI_TX0_RST_GPIO4_C3: J2.136(PWM14_M1/SPI3_CLK_M1/CAN1_RX_M1/PCIE30X2_CLKREQn_M2/I2S3_MCLK_M1/GPIO4_C2_d) ; also on sheet 11
MIPI_DSI_TX1_CLKN: J2.96(MIPI_DSI_TX1_CLKN) ; also on sheet 9
MIPI_DSI_TX1_CLKP: J2.94(MIPI_DSI_TX1_CLKP) ; also on sheet 9
MIPI_DSI_TX1_D0N: J2.104(MIPI_DSI_TX1_D0N) ; also on sheet 9
MIPI_DSI_TX1_D0P: J2.102(MIPI_DSI_TX1_D0P) ; also on sheet 9
MIPI_DSI_TX1_D1N: J2.100(MIPI_DSI_TX1_D1N) ; also on sheet 9
MIPI_DSI_TX1_D1P: J2.98(MIPI_DSI_TX1_D1P) ; also on sheet 9
MIPI_DSI_TX1_D2N: J2.92(MIPI_DSI_TX1_D2N) ; also on sheet 9
MIPI_DSI_TX1_D2P: J2.90(MIPI_DSI_TX1_D2P) ; also on sheet 9
MIPI_DSI_TX1_D3N: J2.88(MIPI_DSI_TX1_D3N) ; also on sheet 9
MIPI_DSI_TX1_D3P: J2.86(MIPI_DSI_TX1_D3P) ; also on sheet 9
MIPI_TX1_BL_PWM12_M0: J2.70(LCDC_D22/PWM12_M0/GMAC1_TXEN_M0/UART3_TX_M1/PDM_SDI2_M2/GPIO3_B7_d) ; also on sheet 9
MIPI_TX1_RST_GPIO2_D4: J2.79(LCDC_D4/VOP_BT656_D4_M0/SPI2_CS1_M1/PCIE30X2_CLKREQn_M1/I2S1_SDI1_M2/GPIO2_D4_d)
MIPI_TX1_RST_GPIO2_D6: J2.75(LCDC_D6/VOP_BT656_D6_M0/SPI2_MOSI_M1/PCIE30X2_PERSTn_M1/I2S1_SDI3_M2/GPIO2_D6_d) ; also on sheet 9
NTC_SARADC_VIN3: J2.5(SARADC_VIN3) ; also on sheet 15
PCIE20_CLKREQn_M2_3V3_L: J2.2(I2S1_SDO1_M0/I2S1_SDI3_M0/PDM_SDI3_M0/PCIE20_CLKREQn_M2/ACODEC_ADC_DATAR/GPIO1_B0_d) ; also on sheet 16
PCIE20_PERSTn_M2_3V3_L: J2.6(I2S1_SDO3_M0/I2S1_SDI1_M0/PDM_SDI1_M0/PCIE20_PERSTn_M2/GPIO1_B2_d) ; also on sheet 16
PCIE20_PRSNT_3V3_L_GPIO3_A6: J2.57(LCDC_D13/VOP_BT1120_CLK/GMAC1_TXCLK_M0/I2S3_SDI_M0/SDMMC2_CLK_M1/GPIO3_A6_d) ; also on sheet 16
PCIE20_REFCLKN: J2.184(PCIE20_REFCLKN) ; also on sheet 16
PCIE20_REFCLKP: J2.182(PCIE20_REFCLKP) ; also on sheet 16
PCIE20_RXN: J2.188(PCIE20_RXN/SATA2_RXN/QSGMII_RXN_M1) ; also on sheet 16
PCIE20_RXP: J2.186(PCIE20_RXP/SATA2_RXP/QSGMII_RXP_M1) ; also on sheet 16
PCIE20_TXN: J2.192(PCIE20_TXN/SATA2_TXN/QSGMII_TXN_M1) ; also on sheet 16
PCIE20_TXP: J2.190(PCIE20_TXP/SATA2_TXP/QSGMII_TXP_M1) ; also on sheet 16
PCIE20_WAKEn_M2_3V3_L: J2.4(I2S1_SDO2_M0/I2S1_SDI2_M0/PDM_SDI2_M0/PCIE20_WAKEn_M2/ACODEC_ADC_SYNC/GPIO1_B1_d) ; also on sheet 16
PWM3_IR: J2.124(PWM3_IR/EDP_HPDIN_M1/PCIE30X1_WAKEn_M0/MCU_JTAG_TMS/GPIO0_C2_d) ; also on sheet 15
PWM13_M1: J2.144(PWM13_M1/SPI3_CS0_M1/SATA0_ACT_LED/UART9_RX_M1/I2S3_SDI_M1/GPIO4_C6_d) ; also on sheet 11
RK809-CLK32K: J2.247(RK809-CLK32K) ; also on sheet 20
RK809_PWRON: J2.251(RK809_PWRON) ; also on sheet 15 19
RK809_VDC: J2.252(RK809_VDC) R7.1 R9.2
SARADC_VIN0_KEY/RECOVERY: J2.1(SARADC_VIN0_KEY/RECOVERY) ; also on sheet 15 19
SARADC_VIN2_HP_HOOK: J2.3(SARADC_VIN2_HP_HOOK) ; also on sheet 15
SARADC_VIN4: J2.7(SARADC_VIN4) ; also on sheet 15
SDMMC0_CLK: J2.206(SDMMC0_CLK/TEST_CLKOUT/UART5_TX_M0/CAN0_RX_M1/GPIO2_A2_d) R21.1
SDMMC0_CLK_: C30.2 D4.1 D4.10 J3.5(CLK) R21.2
SDMMC0_CMD: J2.204(SDMMC0_CMD/PWM10_M1/UART5_RX_M0/CAN0_TX_M1/GPIO2_A1_u) R20.1
SDMMC0_CMD_: D3.5 D3.6 J3.3(CMD) R20.2
SDMMC0_D0: J2.196(SDMMC0_D0/UART2_TX_M1/UART6_TX_M1/PWM8_M1/GPIO1_D5_u) R22.1
SDMMC0_D0_: D4.2 D4.9 J3.7(DATA0) R22.2
SDMMC0_D1: J2.198(SDMMC0_D1/UART2_RX_M1/UART6_RX_M1/PWM9_M1/GPIO1_D6_u) R23.1
SDMMC0_D1_: D4.4 D4.7 J3.8(DATA1) R23.2
SDMMC0_D2: J2.200(SDMMC0_D2/ARMJTAG_TCK/UART5_CTSn_M0/GPIO1_D7_u) R18.1
SDMMC0_D2_: D3.2 D3.9 J3.1(DATA2) R18.2
SDMMC0_D3: J2.202(SDMMC0_D3/ARMJTAG_TMS/UART5_RTSn_M0/GPIO2_A0_u) R19.1
SDMMC0_D3_: D3.4 D3.7 J3.2(CD/DATA3) R19.2
SDMMC0_DET_: D4.5 D4.6 J3.9(CD) R24.2
SDMMC0_DET_L: J2.208(SDMMC0_DET/SATA_CP_DET/PCIE30X1_CLKREQn_M0/GPIO0_A4_u) R24.1
SDMMC2_CLK_M0: J2.27(CIF_D5/EBC_SDDO5/SDMMC2_CLK_M0/I2S1_SDI1_M1/VOP_BT656_D5_M1/GPIO3_D3_d) ; also on sheet 20
SDMMC2_CMD_M0: J2.25(CIF_D4/EBC_SDDO4/SDMMC2_CMD_M0/I2S1_SDI0_M1/VOP_BT656_D4_M1/GPIO3_D2_d) ; also on sheet 20
SDMMC2_D0_M0: J2.17(CIF_D0/EBC_SDDO0/SDMMC2_D0_M0/I2S1_MCLK_M1/VOP_BT656_D0_M1/GPIO3_C6_d) ; also on sheet 20
SDMMC2_D1_M0: J2.19(CIF_D1/EBC_SDDO1/SDMMC2_D1_M0/I2S1_SCLK_TX_M1/VOP_BT656_D1_M1/GPIO3_C7_d) ; also on sheet 20
SDMMC2_D2_M0: J2.21(CIF_D2/EBC_SDDO2/SDMMC2_D2_M0/I2S1_LRCK_TX_M1/VOP_BT656_D2_M1/GPIO3_D0_d) ; also on sheet 20
SDMMC2_D3_M0: J2.23(CIF_D3/EBC_SDDO3/SDMMC2_D3_M0/I2S1_SDO0_M1/VOP_BT656_D3_M1/GPIO3_D1_d) ; also on sheet 20
SPI0_CLK_M1: J2.81(LCDC_D3/VOP_BT656_D3_M0/SPI0_CLK_M1/PCIE30X1_WAKEn_M1/I2S1_SDI0_M2/GPIO2_D3_d) ; also on sheet 15
SPI0_CS0_M1: J2.83(LCDC_D2/VOP_BT656_D2_M0/SPI0_CS0_M1/PCIE30X1_CLKREQn_M1/I2S1_LRCK_TX_M2/GPIO2_D2_d) ; also on sheet 15
SPI0_MISO_M1: J2.87(LCDC_D0/VOP_BT656_D0_M0/SPI0_MISO_M1/PCIE20X1_CLKREQn_M1/I2S1_MCLK_M2/GPIO2_D0_d) ; also on sheet 15
SPI0_MOSI_M1: J2.85(LCDC_D1/VOP_BT656_D1_M0/SPI0_MOSI_M1/PCIE20X1_WAKEn_M1/I2S1_SCLK_TX_M2/GPIO2_D1_d) ; also on sheet 15
SPK_CTL_H_GPIO3_B0: J2.53(LCDC_D15/VOP_BT1120_D6/ETH1_REFCLKO_25M_M0/SDMMC2_PWREN_M1/GPIO3_B0_d) ; also on sheet 8
SPK_MUTE_H_GPIO3_A7: J2.55(LCDC_D14/VOP_BT1120_D5/GMAC1_RXCLK_M0/SDMMC2_DET_M1/GPIO3_A7_d) ; also on sheet 8
SYS_LED_GPIO4_C5: J2.142(PWM12_M1/SPI3_MISO_M1/SATA1_ACT_LED/UART9_TX_M1/I2S3_SDO_M1/GPIO4_C5_d) R8.1
SYS_RESETn: J2.235(SYS_RESETn) ; also on sheet 15
TP0_INT_L_GPIO3_A3: J2.63(LCDC_D10/VOP_BT1120_D2/GMAC1_TXD3_M0/I2S3_SCLK_M0/SDMMC2_D2_M1/GPIO3_A3_d) ; also on sheet 11
TP0_RST_L_GPIO3_A4: J2.61(LCDC_D11/VOP_BT1120_D3/GMAC1_RXD2_M0/I2S3_LRCK_M0/SDMMC2_D3_M1/GPIO3_A4_d) ; also on sheet 11
TP1_INT_L_GPIO3_C0: J2.68(LCDC_D23/PWM13_M0/GMAC1_MCLKINOUT_M0/UART3_RX_M1/PDM_SDI3_M2/GPIO3_C0_d) ; also on sheet 9
TP1_RST_L_GPIO3_C1: J2.66(LCDC_HSYNC/VOP_BT1120_D13/SPI1_MOSI_M1/PCIE20_PERSTn_M1/I2S1_SDO2_M2/GPIO3_C1_d) ; also on sheet 9
TYPEC_CC1: D8.2(I/O1) D11.C J5.A5(CC1) R38.1
TYPEC_CC2: D9.2(I/O1) D13.C J5.B5(CC2) R40.1
UART0_CTSn: J2.134(HDMITX_CEC_M1/PWM0_M1/UART0_CTSn/GPIO0_C7_d) ; also on sheet 15
UART0_RTSn: J2.128(PWM5/SPI0_CS1_M0/UART0_RTSn/GPIO0_C4_d) ; also on sheet 15
UART0_RX: J2.120(PWM1_M0/GPUAVS/UART0_RX/GPIO0_C0_d) ; also on sheet 15
UART0_TX: J2.122(PWM2_M0/NPUAVS/UART0_TX/MCU_JTAG_TDI/GPIO0_C1_d) ; also on sheet 15
UART2_RX_M0: J2.116(UART2_RX_M0/GPIO_D0_u) R25.1
UART2_TX_M0: J2.118(UART2_TX_M0/GPIO_D1_u) R26.1
UART4_RX_M1: J2.82(LCDC_D16/VOP_BT1120_D7/GMAC1_RXD0_M0/UART4_RX_M1/PWM8_M0/GPIO3_B1_d) ; also on sheet 15
UART4_TX_M1: J2.80(LCDC_D17/VOP_BT1120_D8/GMAC1_RXD1_M0/UART4_TX_M1/PWM9_M0/GPIO3_B2_d) ; also on sheet 15
UART5_RX_M1: J2.62(LCDC_DEN/VOP_BT1120_D15/SPI1_CLK_M1/UART5_RX_M1/I2S1_SCLK_RX_M2/GPIO3_C3_d) ; also on sheet 15
UART5_TX_M1: J2.64(LCDC_VSYNC/VOP_BT1120_D14/SPI1_MISO_M1/UART5_TX_M1/I2S1_SDO3_M2/GPIO3_C2_d) ; also on sheet 15
UART7_RX_M1: J2.58(PWM15_IR_M0/SPDIF_TX_M1/GMAC1_MDIO_M0/UART7_RX_M1/I2S1_LRCK_RX_M2/GPIO3_C5_d) ; also on sheet 15
UART7_TX_M1: J2.60(PWM14_M0/VOP_PWM_M1/GMAC1_MDC_M0/UART7_TX_M1/PDM_CLK1_M2/GPIO3_C4_d) ; also on sheet 15
UART8_CTSn_M0: J2.233(SDMMC1_DET/I2C4_SCL_M1/UART8_CTSn_M0/CAN2_TX_M1/GPIO2_B2_u) ; also on sheet 20
UART8_RTSn_M0: J2.231(SDMMC1_PWREN/I2C4_SDA_M1/UART8_RTSn_M0/CAN2_RX_M1/GPIO2_B1_d) ; also on sheet 20
UART8_RX_M0: J2.238(CLK32K_OUT1/UART8_RX_M0/SPI1_CS1_M0/GPIO2_C6_d) ; also on sheet 20
UART8_TX_M0: J2.236(I2S2_SDI_M0/GMAC0_RXER/UART8_TX_M0/SPI2_CS1_M0/GPIO2_C5_d) ; also on sheet 20
USB1_PWREN_H_GPIO3_A5: J2.59(LCDC_D12/VOP_BT1120_D4/GMAC1_RXD3_M0/I2S3_SDO_M0/SDMMC2_CMD_M1/GPIO3_A5_d) R57.1
USB2_HOST2_DM: J2.28(USB2_HOST2_DM) L6.2 R42.1
USB2_HOST2_DM_: D14.5 D14.6 J6.2(1D-) L6.3 R42.2
USB2_HOST2_DP: J2.26(USB2_HOST2_DP) L6.1 R43.1
USB2_HOST2_DP_: D14.4 D14.7 J6.3(1D+) L6.4 R43.2
USB2_HOST2_PWREN_H_GPIO0_A6: J2.110(GPU_PWREN/SATA_CP_POD/PCIE30X2_CLKREQn_M0/GPIO0_A6_d) U5.4(EN)
USB2_HOST3_DM: J2.24(USB2_HOST3_DM) R71.2
USB2_HOST3_DP: J2.22(USB2_HOST3_DP) R69.2
USB2_PWREN_H_GPIO4_C3: J2.138(PWM15_IR_M1/SPI3_MOSI_M1/CAN1_TX_M1/PCIE30X2_WAKEn_M2/I2S3_SCLK_M1/GPIO4_C3_d) R70.1
USB3_HOST1_DM: J2.169(USB3_HOST1_DM) L7.2 R46.1
USB3_HOST1_DM_: D14.2 D14.9 J6.11(2D-) L7.3 R46.2
USB3_HOST1_DP: J2.167(USB3_HOST1_DP) L7.1 R47.1
USB3_HOST1_DP_: D14.1 D14.10 J6.12(2D+) L7.4 R47.2
USB3_HOST1_PWREN_H_GPIO3_A0: J2.71(LCDC_CLK/VOP_BT656_CLK_M0/SPI2_CLK_M1/UART8_RX_M1/I2S1_SDO1_M2/GPIO3_A0_d) U6.4(EN)
USB3_HOST1_SSRXN: J2.175(USB3_HOST1_SSRXN/SATA1_RXN/QSGMII_RXN_M0) R375.1 ; also on sheet 18
USB3_HOST1_SSRXN_: D17.1 D17.10 J6.14(RX2-) R375.2
USB3_HOST1_SSRXP: J2.177(USB3_HOST1_SSRXP/SATA1_RXP/QSGMII_RXP_M0) R376.1 ; also on sheet 18
USB3_HOST1_SSRXP_: D17.2 D17.9 J6.15(RX+) R376.2
USB3_HOST1_SSTXN: C290.1 J2.171(USB3_HOST1_SSTXN/SATA1_TXN/QSGMII_TXN_M0) ; also on sheet 18
USB3_HOST1_SSTXN_: C290.2 D17.4 D17.7 J6.17(TX2-)
USB3_HOST1_SSTXP: C291.1 J2.173(USB3_HOST1_SSTXP/SATA1_TXP/QSGMII_TXP_M0) ; also on sheet 18
USB3_HOST1_SSTXP_: C291.2 D17.5 D17.6 J6.18(TX2+)
USB3_OTG0_DM: J2.189(USB3_OTG0_DM) L5.2 R29.1
USB3_OTG0_DM_: D12.2(I/O1) J5.A7(DM1) J5.B7(DM2) L5.3 R29.2
USB3_OTG0_DP: J2.187(USB3_OTG0_DP) L5.1 R34.1
USB3_OTG0_DP_: D10.2(I/O1) J5.A6(DP1) J5.B6(DP2) L5.4 R34.2
USB3_OTG0_ID: J2.193(USB3_OTG0_ID) Q1.3(DRAIN) R31.2
USB3_OTG0_SSRXN: J2.183(USB3_OTG0_SSRXN/SATA0_RXN) R48.1
USB3_OTG0_SSRXN_: D107.1 D107.10 J6.5(RX1-) R48.2
USB3_OTG0_SSRXP: J2.185(USB3_OTG0_SSRXP/SATA0_RXP) R49.1
USB3_OTG0_SSRXP_: D107.2 D107.9 J6.6(RX1+) R49.2
USB3_OTG0_SSTXN: C39.1 J2.179(USB3_OTG0_SSTXN/SATA0_TXN)
USB3_OTG0_SSTXN_: C39.2 D107.4 D107.7 J6.8(TX1-)
USB3_OTG0_SSTXP: C41.1 J2.181(USB3_OTG0_SSTXP/SATA0_TXP)
USB3_OTG0_SSTXP_: C41.2 D107.5 D107.6 J6.9(TX1+)
USB3_OTG0_VBUSDET: J2.191(USB3_OTG0_VBUSDET) R27.2 R28.2
USB3_PWREN_H_GPIO4_C4: J2.140(EDP_HPDIN_M0/SPDIF_TX_M2/SATA2_ACT_LED/PCIE30X2_PERSTn_M2/I2S3_LRCK_M1/GPIO4_C4_d) R77.1
USB_OTG_PWREN_H_GPIO0_A5: J2.212(SDMMC0_PWREN/SATA_MP_SWITCH/PCIE20_CLKREQn_M0/GPIO0_A5_d) R32.1
WIFI_PWREN_L_GPIO0_B7: J2.114(PWM0-M0/CPUAVS/GPIO0_B7_d) ; also on sheet 20
WIFI_REG_ON_H_GPIO3_D5: J2.33(CIF_D7/EBC_SDDO7/SDMMC2_PWREN_M0/I2S1_SDI3_M1/VOP_BT656_D7_M1/GPIO3_D5_d) ; also on sheet 20
WIFI_WAKE_HOST_H_GPIO3_D4: J2.29(CIF_D6/EBC_SDDO6/SDMMC2_DET_M0/I2S1_SDI2_M1/VOP_BT656_D6_M1/GPIO3_D4_d) ; also on sheet 20
N69300963: C2.2 D1.A(I/O2) F2.2 L1.1 R1.1
N69811939: C12.2 R3.1 R5.2 U1.5(EN)
N69812073: C1.1 L2.1 U1.2(LX)
N69812091: C1.2 U1.4(BS)
N69812134: C8.1 R4.1 R6.2 U1.6(FB)
N69812831: C13.1 L3.1 U2.2(LX)
N69812843: C17.1 R11.1 R12.2 U2.6(FB)
N69812998: C13.2 U2.4(BS)
N69813915: R13.2 U2.5(EN)
N69814391: L4.1 U3.3(SW)
N69814410: C24.1 R15.1 R16.2 U3.5(FB)
N69814930: R14.2 U3.1(EN)
N69815076: LED1.3 R10.2
N69815079: LED1.1 R8.2
N69817092: D5.2(I/O1) J4.1 R25.2
N69817095: D6.2(I/O1) J4.2 R26.2
N69818339: R58.1 U8.1(OVCB_2)
N69818343: R55.1 U8.7(OVCB_4)
N69818347: R54.1 U8.5(OVCB_3)
N69818991: C44.2 R61.1 U8.39(VD33_OUT)
N69818999: R59.2 U8.48(OVCB_1)
N69819001: R65.2 U8.36(BUS_B)
N69819016: R73.1 U8.28(REXT)
N69819018: C45.2 U8.38(VD5_IN)
N69820056: R45.2 U5.3(OCB)
N69820298: R51.2 U6.3(OCB)
N69820533: R57.2 U7.4(EN)
N69820554: R60.2 U7.3(OCB)
N69820805: R70.2 U9.4(EN)
N69820826: R72.2 U9.3(OCB)
N69821095: R77.2 U10.4(EN)
N69821116: R79.2 U10.3(OCB)
N69821410: R32.2 R36.2 U4.4(EN)
N69821431: R33.2 U4.3(OCB)
N69829177: Q1.1(GATE) Q2.3(DRAIN) R30.1 R31.1 R35.2
N69829182: D11.A D13.A R37.1 R38.2 R39.1 R40.2
N69829189: C35.2 Q2.1(GATE) R35.1 R39.2 R41.2

Not connected (* = marked no-connect by the designer): D3 1 10; J1 1(NC) 5(TH1) 6(TH2); J2 160(PCIE30_RX1N) 162(PCIE30_RX1P) 164(PCIE30_RX0N) 166(PCIE30_RX0P) 168(PCIE30_TX1N) 170(PCIE30_TX1P) 172(PCIE30_TX0N) 174(PCIE30_TX0P) 176(PCIE30_REFCLKN_IN) 178(PCIE30_REFCLKP_IN) 239(BATDIV) 241(SNSP) 243(SNSN); J5 A8(SBU1)* B8(SBU2)* NC1 NC2; MARK1 1; MARK2 1; MARK3 1; MARK4 1; U8 2(PWRB)* 4(PWRB_3)* 8(PWRB_4)* 43(LED_1)* 44(LED_2)* 45(LED_3)* 46(LED_4)* 47(PWRB_1)*

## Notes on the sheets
sheet 1
- Revision History
- Version
- Date
- Author
- Change Note
- Approved
- V1A
- 2020.08.20
- First edition
sheet 2
- RK3568 Ref Block Diagram
- HDR200MA-2X10
- Camera
  OV8858
- Camera
  OV5648 X2
- HDMI2.0 TX
- LVDS
- RJ-45
- RJ-45
- CEC
  HDMI_I2C
  HPD
- I2C5
- I2C4
- Panel
- Panel
- DOG
- Debug
  UART2
- WIFI/BT
- Giga PHY
- Giga PHY
- AP6236
- RTL8211F-CG
- RTL8211F-CG
- KEY
- HR7P153
  P4SA_BM
- TP
  I2C1
- TP
  I2C2
- 4 Lane MIPI DSI or LVDS
- UART2
- GPIO×3
- x 4 Lane
- x 4 Lane
- x 2 Lane X2
- GPIO×2
- SYS_LED
- x 4 Lane
- 4G_LED
- TMDS
- SD
- SDMMC2 x 4bit
- CEC
  HDMI_I2C
  HPD
- UART1/PCM2
- PMUIO1
  PMUIO2
- HDMI2.0
  TX
- MIPI
  DSI
  LVDS
  TX0
- MIPI
  DSI
  TX1
- MIPI CSI RX
- VCCIO4
- VCCIO7
- RGMII0
- I2C2
- VCCIO6
- RGMII1_M1
- VCCIO6
- PCIE2.0
- PCIE2.0
- NVME接口
- INDUSTIO
- USB2.0
  HOST2
- USB3.0
  HOST
  A座
- MULTI_
  PHY2
- PCIE2.0
  SATA2
  QSGMII_M1
- SS
- SS
- HOST2_LS/FS/HS
- USB3_HOST1_SS
- MULTI_
  PHY1
- USB3_HOST1
  SATA1
  QSGMII_M0
- USB2
  HOST2
  HOST3
- USB4
- HOST3_LS/FS/HS
- FE1.1
  HUB
- USB3_OTG0_SS
- USB1&2&3
- USB2.0 x3
- MULTI_
  PHY0
- USB3_OTG0
  SATA0
- SOM3568-CORE
- 4G/5G模块 MiniPCIE
- USB4
- SDMMC0 x 4bit
- VCCIO3
- PH4p × 3
- Quad A55
- USB2
  OTG0
  HOST1
- Micro
  SD Card
- USB3.0
  OTG0
  TYPE-C
- USB2_OTG0_LS/FS/HS
- GPIO×8
- Micro
  SD Card
- SS
- VCCIO5
- SPI+UART+IE+PWM+SPI+I2C
- HDR200MA-2X10
- eDP
- DC/DC
- Power for SOM3568
- MAIN
  POWER
- SARADC_IN0
- 5.0V
- RK809-5
- VCCIO1
- SARADC
- 12V
  Adapter
- HPOUT
- MIC1
- I2C3
- I2S1
- HDR254MRA-2X15
- Power Key
- 功放NS4205
- RTC
  HYM8563
- Headphone
- Keys
- 4R@3W x 2
sheet 3
- DCDC
- VCC3V3_SD
- 12V
- SOM3568-V2
- Micro
  SD Card
- ETA1654
- VCC5V0_SYS
- DCDC
- 5V
- 5V
- ETA1654
- VCC_5V
- HDMI
- VCC_5V
- LVDS
- DCDC
- ETA3417
- VDD_3V3
- VDD_3V3
- EDP
- SY7201ABC
- 3.3V
- PCIE3.0
- MIPI DSI TX0
- SY7201ABC
- AP6236
- MIPI DSI TX1
- LDO
- ETA5050
- VCC2V8_DVP
- FE1.1
- LDO
- DCDC
- Camera
- ETA5050
- ETA3417
- VCC1V8_DVP
- VCC_3V8
- RTL8211F-CG
- LDO
- 3.8V
- ETA5050
- VCC1V2_DVP
- MINI_PCIE
  4G/5G
sheet 4
- DC IN
- Note:Please
  use a 12V DC.
- VCC5V_SYS
- VCC_5V
- VDC
- LED
- VDD_3V3
sheet 6
- SD Card
- Debug UART2
sheet 7
- OTG
- 单路时贴68K ,组合CC检测时贴15K
- USB HSOT
- USB2.0 *3
- USB2.0 HUB-FE1.1
- 内部偏值参考电阻
